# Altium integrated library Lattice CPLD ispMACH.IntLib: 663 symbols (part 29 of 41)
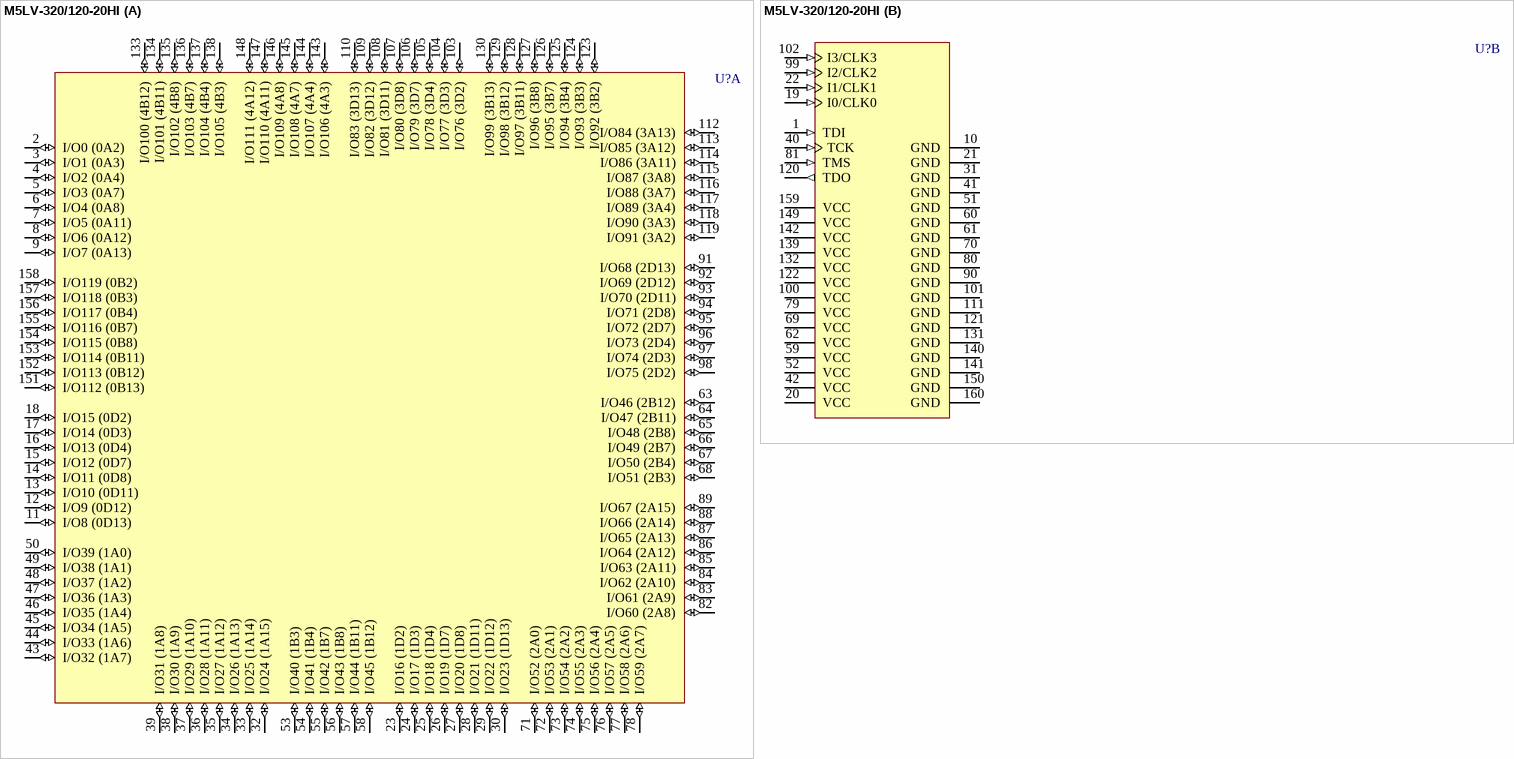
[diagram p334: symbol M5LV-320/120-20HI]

## M5LV-320/120-20HI
designator U?
High-Density and High-I/O Complex PLD
footprint MQFP160_N (QFP, 160-Leads, Body 27.7 x 27.7mm, Pitch 0.65mm, IPC Medium Density)
footprint MQFP160_L (QFP, 160-Leads, Body 27.7 x 27.7mm, Pitch 0.65mm, IPC High Density)
footprint MQFP160_M (QFP, 160-Leads, Body 27.7 x 27.7mm, Pitch 0.65mm, IPC Low Density)
3D model M5LV-MQFP160 (160-Pin Quad Flat Pack 0.65 mm Pitch)
part A pins: 2 I/O0 (0A2) (io), 3 I/O1 (0A3) (io), 4 I/O2 (0A4) (io), 5 I/O3 (0A7) (io), 6 I/O4 (0A8) (io), 7 I/O5 (0A11) (io), 8 I/O6 (0A12) (io), 9 I/O7 (0A13) (io), 11 I/O8 (0D13) (io), 12 I/O9 (0D12) (io), 13 I/O10 (0D11) (io), 14 I/O11 (0D8) (io), 15 I/O12 (0D7) (io), 16 I/O13 (0D4) (io), 17 I/O14 (0D3) (io), 18 I/O15 (0D2) (io), 23 I/O16 (1D2) (io), 24 I/O17 (1D3) (io), 25 I/O18 (1D4) (io), 26 I/O19 (1D7) (io), 27 I/O20 (1D8) (io), 28 I/O21 (1D11) (io), 29 I/O22 (1D12) (io), 30 I/O23 (1D13) (io), 32 I/O24 (1A15) (io), 33 I/O25 (1A14) (io), 34 I/O26 (1A13) (io), 35 I/O27 (1A12) (io), 36 I/O28 (1A11) (io), 37 I/O29 (1A10) (io), 38 I/O30 (1A9) (io), 39 I/O31 (1A8) (io), 43 I/O32 (1A7) (io), 44 I/O33 (1A6) (io), 45 I/O34 (1A5) (io), 46 I/O35 (1A4) (io), 47 I/O36 (1A3) (io), 48 I/O37 (1A2) (io), 49 I/O38 (1A1) (io), 50 I/O39 (1A0) (io), 53 I/O40 (1B3) (io), 54 I/O41 (1B4) (io), 55 I/O42 (1B7) (io), 56 I/O43 (1B8) (io), 57 I/O44 (1B11) (io), 58 I/O45 (1B12) (io), 63 I/O46 (2B12) (io), 64 I/O47 (2B11) (io), 65 I/O48 (2B8) (io), 66 I/O49 (2B7) (io), 67 I/O50 (2B4) (io), 68 I/O51 (2B3) (io), 71 I/O52 (2A0) (io), 72 I/O53 (2A1) (io), 73 I/O54 (2A2) (io), 74 I/O55 (2A3) (io), 75 I/O56 (2A4) (io), 76 I/O57 (2A5) (io), 77 I/O58 (2A6) (io), 78 I/O59 (2A7) (io), 82 I/O60 (2A8) (io), 83 I/O61 (2A9) (io), 84 I/O62 (2A10) (io), 85 I/O63 (2A11) (io), 86 I/O64 (2A12) (io), 87 I/O65 (2A13) (io), 88 I/O66 (2A14) (io), 89 I/O67 (2A15) (io), 91 I/O68 (2D13) (io), 92 I/O69 (2D12) (io), 93 I/O70 (2D11) (io), 94 I/O71 (2D8) (io), 95 I/O72 (2D7) (io), 96 I/O73 (2D4) (io), 97 I/O74 (2D3) (io), 98 I/O75 (2D2) (io), 103 I/O76 (3D2) (io), 104 I/O77 (3D3) (io), 105 I/O78 (3D4) (io), 106 I/O79 (3D7) (io), 107 I/O80 (3D8) (io), 108 I/O81 (3D11) (io), 109 I/O82 (3D12) (io), 110 I/O83 (3D13) (io), 112 I/O84 (3A13) (io), 113 I/O85 (3A12) (io), 114 I/O86 (3A11) (io), 115 I/O87 (3A8) (io), 116 I/O88 (3A7) (io), 117 I/O89 (3A4) (io), 118 I/O90 (3A3) (io), 119 I/O91 (3A2) (io), 123 I/O92 (3B2) (io), 124 I/O93 (3B3) (io), 125 I/O94 (3B4) (io), 126 I/O95 (3B7) (io), 127 I/O96 (3B8) (io), 128 I/O97 (3B11) (io), 129 I/O98 (3B12) (io), 130 I/O99 (3B13) (io), 133 I/O100 (4B12) (io), 134 I/O101 (4B11) (io), 135 I/O102 (4B8) (io), 136 I/O103 (4B7) (io), 137 I/O104 (4B4) (io), 138 I/O105 (4B3) (io), 143 I/O106 (4A3) (io), 144 I/O107 (4A4) (io), 145 I/O108 (4A7) (io), 146 I/O109 (4A8) (io), 147 I/O110 (4A11) (io), 148 I/O111 (4A12) (io), 151 I/O112 (0B13) (io), 152 I/O113 (0B12) (io), 153 I/O114 (0B11) (io), 154 I/O115 (0B8) (io), 155 I/O116 (0B7) (io), 156 I/O117 (0B4) (io), 157 I/O118 (0B3) (io), 158 I/O119 (0B2) (io)
part B pins: 1 TDI (in), 10 GND (power), 19 I0/CLK0 (in), 20 VCC (power), 21 GND (power), 22 I1/CLK1 (in), 31 GND (power), 40 TCK (in), 41 GND (power), 42 VCC (power), 51 GND (power), 52 VCC (power), 59 VCC (power), 60 GND (power), 61 GND (power), 62 VCC (power), 69 VCC (power), 70 GND (power), 79 VCC (power), 80 GND (power), 81 TMS (in), 90 GND (power), 99 I2/CLK2 (in), 100 VCC (power), 101 GND (power), 102 I3/CLK3 (in), 111 GND (power), 120 TDO (out), 121 GND (power), 122 VCC (power), 131 GND (power), 132 VCC (power), 139 VCC (power), 140 GND (power), 141 GND (power), 142 VCC (power), 149 VCC (power), 150 GND (power), 159 VCC (power), 160 GND (power)

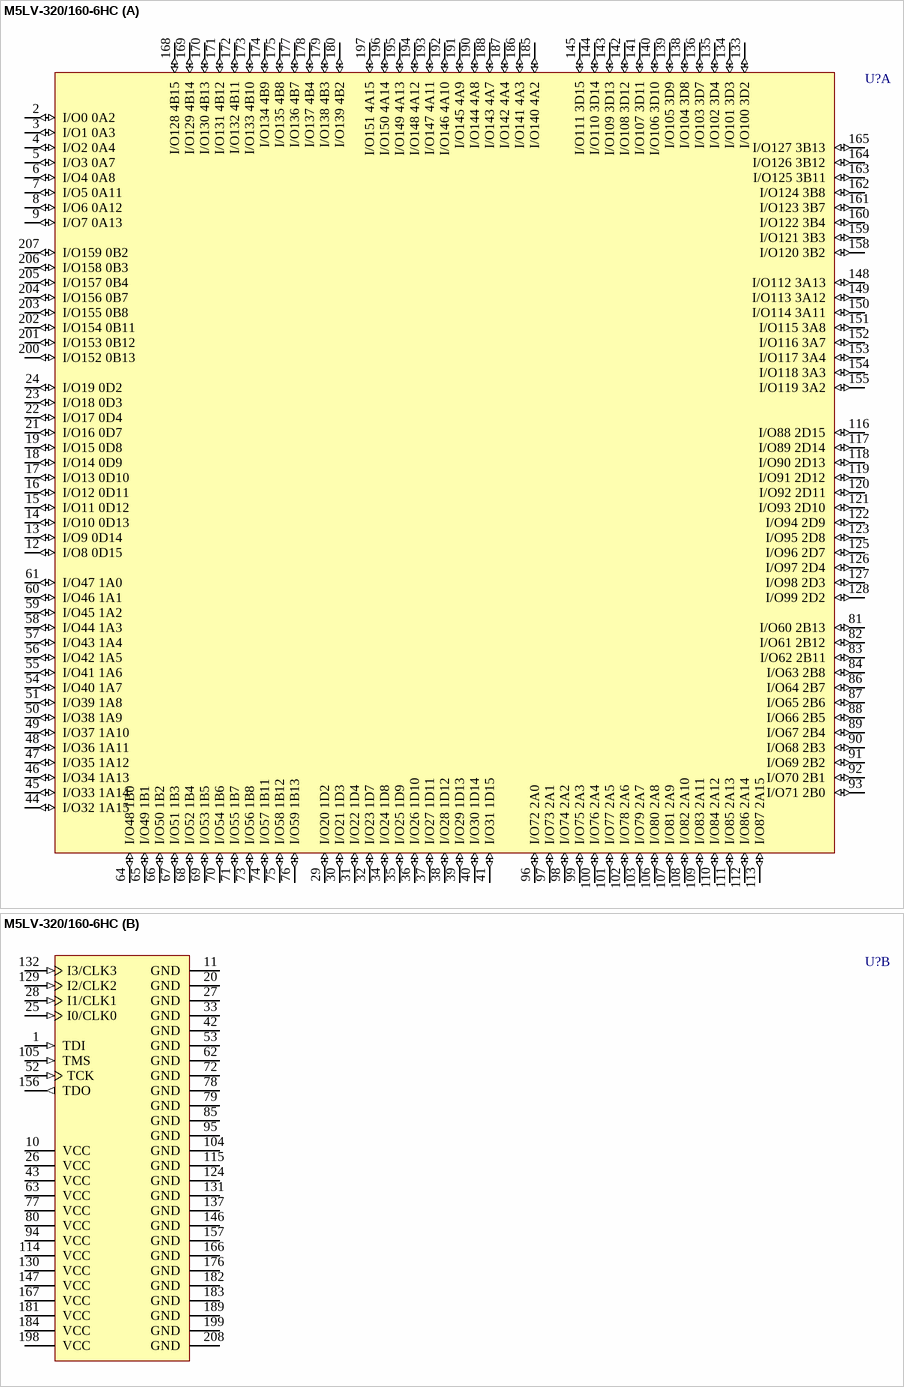
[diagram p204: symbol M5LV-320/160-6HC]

## M5LV-320/160-6HC
designator U?
High-Density and High-I/O Complex PLD
footprint MQFP208_N (Shrink QFP, 208-Leads, Body 27.7x27.7mm, Pitch 0.5mm, IPC Medium Density)
footprint MQFP208_L (Shrink QFP, 208-Leads, Body 27.7x27.7mm, Pitch 0.5mm, IPC High Density)
footprint MQFP208_M (Shrink QFP, 208-Leads, Body 27.7x27.7mm, Pitch 0.5mm, IPC Low Density)
3D model M5LV-MQFP208 (208-Pin Shrink Quad Flat Pack 0.5 mm Pitch)
part A pins: 2 I/O0 0A2 (io), 3 I/O1 0A3 (io), 4 I/O2 0A4 (io), 5 I/O3 0A7 (io), 6 I/O4 0A8 (io), 7 I/O5 0A11 (io), 8 I/O6 0A12 (io), 9 I/O7 0A13 (io), 12 I/O8 0D15 (io), 13 I/O9 0D14 (io), 14 I/O10 0D13 (io), 15 I/O11 0D12 (io), 16 I/O12 0D11 (io), 17 I/O13 0D10 (io), 18 I/O14 0D9 (io), 19 I/O15 0D8 (io), 21 I/O16 0D7 (io), 22 I/O17 0D4 (io), 23 I/O18 0D3 (io), 24 I/O19 0D2 (io), 29 I/O20 1D2 (io), 30 I/O21 1D3 (io), 31 I/O22 1D4 (io), 32 I/O23 1D7 (io), 34 I/O24 1D8 (io), 35 I/O25 1D9 (io), 36 I/O26 1D10 (io), 37 I/O27 1D11 (io), 38 I/O28 1D12 (io), 39 I/O29 1D13 (io), 40 I/O30 1D14 (io), 41 I/O31 1D15 (io), 44 I/O32 1A15 (io), 45 I/O33 1A14 (io), 46 I/O34 1A13 (io), 47 I/O35 1A12 (io), 48 I/O36 1A11 (io), 49 I/O37 1A10 (io), 50 I/O38 1A9 (io), 51 I/O39 1A8 (io), 54 I/O40 1A7 (io), 55 I/O41 1A6 (io), 56 I/O42 1A5 (io), 57 I/O43 1A4 (io), 58 I/O44 1A3 (io), 59 I/O45 1A2 (io), 60 I/O46 1A1 (io), 61 I/O47 1A0 (io), 64 I/O48 1B0 (io), 65 I/O49 1B1 (io), 66 I/O50 1B2 (io), 67 I/O51 1B3 (io), 68 I/O52 1B4 (io), 69 I/O53 1B5 (io), 70 I/O54 1B6 (io), 71 I/O55 1B7 (io), 73 I/O56 1B8 (io), 74 I/O57 1B11 (io), 75 I/O58 1B12 (io), 76 I/O59 1B13 (io), 81 I/O60 2B13 (io), 82 I/O61 2B12 (io), 83 I/O62 2B11 (io), 84 I/O63 2B8 (io), 86 I/O64 2B7 (io), 87 I/O65 2B6 (io), 88 I/O66 2B5 (io), 89 I/O67 2B4 (io), 90 I/O68 2B3 (io), 91 I/O69 2B2 (io), 92 I/O70 2B1 (io), 93 I/O71 2B0 (io), 96 I/O72 2A0 (io), 97 I/O73 2A1 (io), 98 I/O74 2A2 (io), 99 I/O75 2A3 (io), 100 I/O76 2A4 (io), 101 I/O77 2A5 (io), 102 I/O78 2A6 (io), 103 I/O79 2A7 (io), 106 I/O80 2A8 (io), 107 I/O81 2A9 (io), 108 I/O82 2A10 (io), 109 I/O83 2A11 (io), 110 I/O84 2A12 (io), 111 I/O85 2A13 (io), 112 I/O86 2A14 (io), 113 I/O87 2A15 (io), 116 I/O88 2D15 (io), 117 I/O89 2D14 (io), 118 I/O90 2D13 (io), 119 I/O91 2D12 (io), 120 I/O92 2D11 (io), 121 I/O93 2D10 (io), 122 I/O94 2D9 (io), 123 I/O95 2D8 (io), 125 I/O96 2D7 (io), 126 I/O97 2D4 (io), 127 I/O98 2D3 (io), 128 I/O99 2D2 (io), 133 I/O100 3D2 (io), 134 I/O101 3D3 (io), 135 I/O102 3D4 (io), 136 I/O103 3D7 (io), 138 I/O104 3D8 (io), 139 I/O105 3D9 (io), 140 I/O106 3D10 (io), 141 I/O107 3D11 (io), 142 I/O108 3D12 (io), 143 I/O109 3D13 (io), 144 I/O110 3D14 (io), 145 I/O111 3D15 (io), 148 I/O112 3A13 (io), 149 I/O113 3A12 (io), 150 I/O114 3A11 (io), 151 I/O115 3A8 (io), 152 I/O116 3A7 (io), 153 I/O117 3A4 (io), 154 I/O118 3A3 (io), 155 I/O119 3A2 (io), 158 I/O120 3B2 (io), 159 I/O121 3B3 (io), 160 I/O122 3B4 (io), 161 I/O123 3B7 (io), 162 I/O124 3B8 (io), 163 I/O125 3B11 (io), 164 I/O126 3B12 (io), 165 I/O127 3B13 (io), 168 I/O128 4B15 (io), 169 I/O129 4B14 (io), 170 I/O130 4B13 (io), 171 I/O131 4B12 (io), 172 I/O132 4B11 (io), 173 I/O133 4B10 (io), 174 I/O134 4B9 (io), 175 I/O135 4B8 (io), 177 I/O136 4B7 (io), 178 I/O137 4B4 (io), 179 I/O138 4B3 (io), 180 I/O139 4B2 (io), 185 I/O140 4A2 (io), 186 I/O141 4A3 (io), 187 I/O142 4A4 (io), 188 I/O143 4A7 (io), 190 I/O144 4A8 (io), 191 I/O145 4A9 (io), 192 I/O146 4A10 (io), 193 I/O147 4A11 (io), 194 I/O148 4A12 (io), 195 I/O149 4A13 (io), 196 I/O150 4A14 (io), 197 I/O151 4A15 (io), 200 I/O152 0B13 (io), 201 I/O153 0B12 (io), 202 I/O154 0B11 (io), 203 I/O155 0B8 (io), 204 I/O156 0B7 (io), 205 I/O157 0B4 (io), 206 I/O158 0B3 (io), 207 I/O159 0B2 (io)
part B pins: 1 TDI (in), 10 VCC (power), 11 GND (power), 20 GND (power), 25 I0/CLK0 (in), 26 VCC (power), 27 GND (power), 28 I1/CLK1 (in), 33 GND (power), 42 GND (power), 43 VCC (power), 52 TCK (in), 53 GND (power), 62 GND (power), 63 VCC (power), 72 GND (power), 77 VCC (power), 78 GND (power), 79 GND (power), 80 VCC (power), 85 GND (power), 94 VCC (power), 95 GND (power), 104 GND (power), 105 TMS (in), 114 VCC (power), 115 GND (power), 124 GND (power), 129 I2/CLK2 (in), 130 VCC (power), 131 GND (power), 132 I3/CLK3 (in), 137 GND (power), 146 GND (power), 147 VCC (power), 156 TDO (out), 157 GND (power), 166 GND (power), 167 VCC (power), 176 GND (power), 181 VCC (power), 182 GND (power), 183 GND (power), 184 VCC (power), 189 GND (power), 198 VCC (power), 199 GND (power), 208 GND (power)

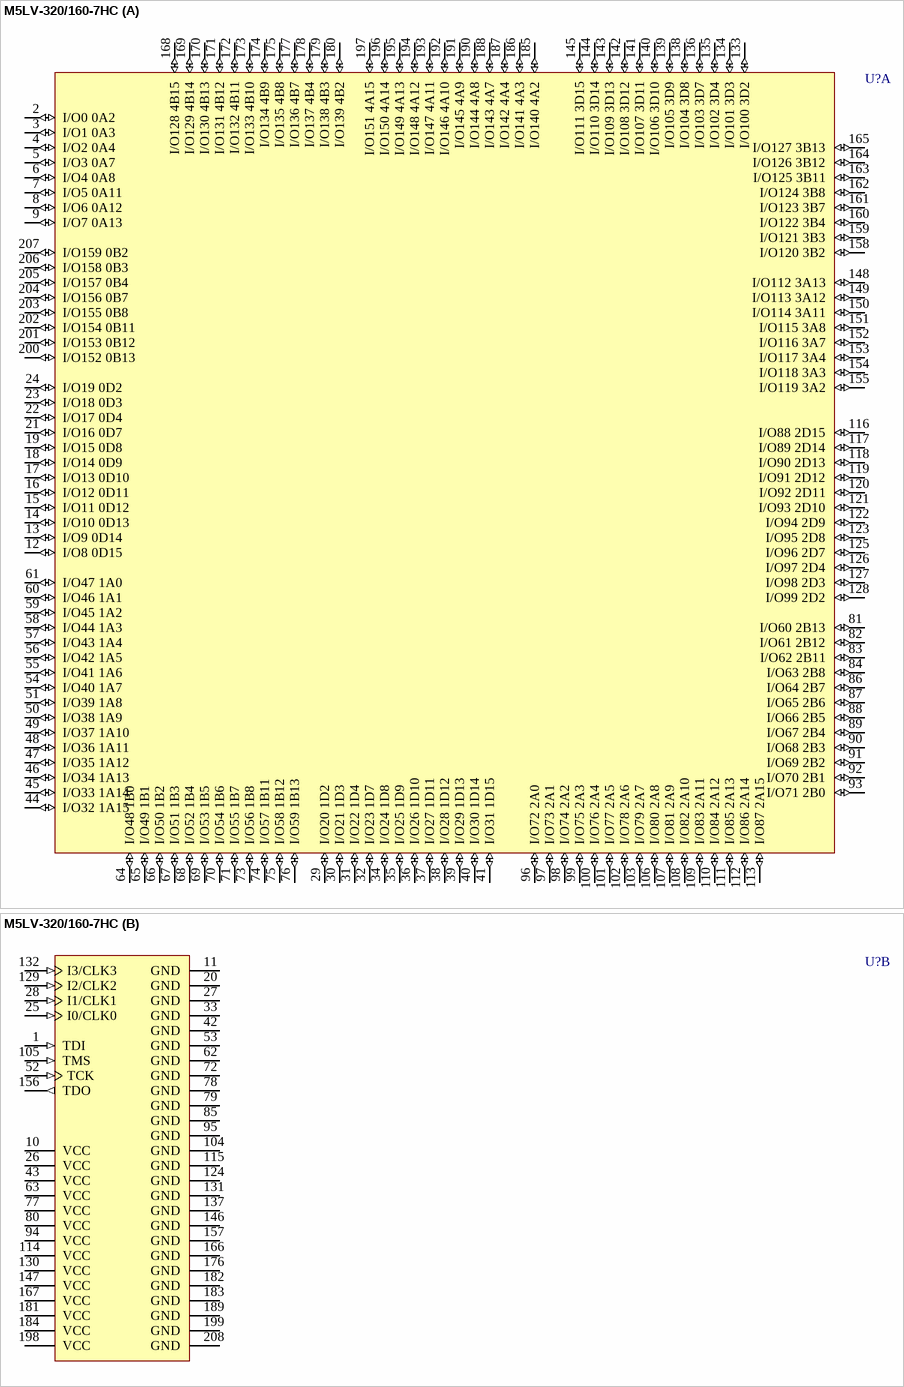
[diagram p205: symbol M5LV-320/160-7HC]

## M5LV-320/160-7HC
designator U?
High-Density and High-I/O Complex PLD
footprint MQFP208_N (Shrink QFP, 208-Leads, Body 27.7x27.7mm, Pitch 0.5mm, IPC Medium Density)
footprint MQFP208_L (Shrink QFP, 208-Leads, Body 27.7x27.7mm, Pitch 0.5mm, IPC High Density)
footprint MQFP208_M (Shrink QFP, 208-Leads, Body 27.7x27.7mm, Pitch 0.5mm, IPC Low Density)
3D model M5LV-MQFP208 (208-Pin Shrink Quad Flat Pack 0.5 mm Pitch)
part A pins: 2 I/O0 0A2 (io), 3 I/O1 0A3 (io), 4 I/O2 0A4 (io), 5 I/O3 0A7 (io), 6 I/O4 0A8 (io), 7 I/O5 0A11 (io), 8 I/O6 0A12 (io), 9 I/O7 0A13 (io), 12 I/O8 0D15 (io), 13 I/O9 0D14 (io), 14 I/O10 0D13 (io), 15 I/O11 0D12 (io), 16 I/O12 0D11 (io), 17 I/O13 0D10 (io), 18 I/O14 0D9 (io), 19 I/O15 0D8 (io), 21 I/O16 0D7 (io), 22 I/O17 0D4 (io), 23 I/O18 0D3 (io), 24 I/O19 0D2 (io), 29 I/O20 1D2 (io), 30 I/O21 1D3 (io), 31 I/O22 1D4 (io), 32 I/O23 1D7 (io), 34 I/O24 1D8 (io), 35 I/O25 1D9 (io), 36 I/O26 1D10 (io), 37 I/O27 1D11 (io), 38 I/O28 1D12 (io), 39 I/O29 1D13 (io), 40 I/O30 1D14 (io), 41 I/O31 1D15 (io), 44 I/O32 1A15 (io), 45 I/O33 1A14 (io), 46 I/O34 1A13 (io), 47 I/O35 1A12 (io), 48 I/O36 1A11 (io), 49 I/O37 1A10 (io), 50 I/O38 1A9 (io), 51 I/O39 1A8 (io), 54 I/O40 1A7 (io), 55 I/O41 1A6 (io), 56 I/O42 1A5 (io), 57 I/O43 1A4 (io), 58 I/O44 1A3 (io), 59 I/O45 1A2 (io), 60 I/O46 1A1 (io), 61 I/O47 1A0 (io), 64 I/O48 1B0 (io), 65 I/O49 1B1 (io), 66 I/O50 1B2 (io), 67 I/O51 1B3 (io), 68 I/O52 1B4 (io), 69 I/O53 1B5 (io), 70 I/O54 1B6 (io), 71 I/O55 1B7 (io), 73 I/O56 1B8 (io), 74 I/O57 1B11 (io), 75 I/O58 1B12 (io), 76 I/O59 1B13 (io), 81 I/O60 2B13 (io), 82 I/O61 2B12 (io), 83 I/O62 2B11 (io), 84 I/O63 2B8 (io), 86 I/O64 2B7 (io), 87 I/O65 2B6 (io), 88 I/O66 2B5 (io), 89 I/O67 2B4 (io), 90 I/O68 2B3 (io), 91 I/O69 2B2 (io), 92 I/O70 2B1 (io), 93 I/O71 2B0 (io), 96 I/O72 2A0 (io), 97 I/O73 2A1 (io), 98 I/O74 2A2 (io), 99 I/O75 2A3 (io), 100 I/O76 2A4 (io), 101 I/O77 2A5 (io), 102 I/O78 2A6 (io), 103 I/O79 2A7 (io), 106 I/O80 2A8 (io), 107 I/O81 2A9 (io), 108 I/O82 2A10 (io), 109 I/O83 2A11 (io), 110 I/O84 2A12 (io), 111 I/O85 2A13 (io), 112 I/O86 2A14 (io), 113 I/O87 2A15 (io), 116 I/O88 2D15 (io), 117 I/O89 2D14 (io), 118 I/O90 2D13 (io), 119 I/O91 2D12 (io), 120 I/O92 2D11 (io), 121 I/O93 2D10 (io), 122 I/O94 2D9 (io), 123 I/O95 2D8 (io), 125 I/O96 2D7 (io), 126 I/O97 2D4 (io), 127 I/O98 2D3 (io), 128 I/O99 2D2 (io), 133 I/O100 3D2 (io), 134 I/O101 3D3 (io), 135 I/O102 3D4 (io), 136 I/O103 3D7 (io), 138 I/O104 3D8 (io), 139 I/O105 3D9 (io), 140 I/O106 3D10 (io), 141 I/O107 3D11 (io), 142 I/O108 3D12 (io), 143 I/O109 3D13 (io), 144 I/O110 3D14 (io), 145 I/O111 3D15 (io), 148 I/O112 3A13 (io), 149 I/O113 3A12 (io), 150 I/O114 3A11 (io), 151 I/O115 3A8 (io), 152 I/O116 3A7 (io), 153 I/O117 3A4 (io), 154 I/O118 3A3 (io), 155 I/O119 3A2 (io), 158 I/O120 3B2 (io), 159 I/O121 3B3 (io), 160 I/O122 3B4 (io), 161 I/O123 3B7 (io), 162 I/O124 3B8 (io), 163 I/O125 3B11 (io), 164 I/O126 3B12 (io), 165 I/O127 3B13 (io), 168 I/O128 4B15 (io), 169 I/O129 4B14 (io), 170 I/O130 4B13 (io), 171 I/O131 4B12 (io), 172 I/O132 4B11 (io), 173 I/O133 4B10 (io), 174 I/O134 4B9 (io), 175 I/O135 4B8 (io), 177 I/O136 4B7 (io), 178 I/O137 4B4 (io), 179 I/O138 4B3 (io), 180 I/O139 4B2 (io), 185 I/O140 4A2 (io), 186 I/O141 4A3 (io), 187 I/O142 4A4 (io), 188 I/O143 4A7 (io), 190 I/O144 4A8 (io), 191 I/O145 4A9 (io), 192 I/O146 4A10 (io), 193 I/O147 4A11 (io), 194 I/O148 4A12 (io), 195 I/O149 4A13 (io), 196 I/O150 4A14 (io), 197 I/O151 4A15 (io), 200 I/O152 0B13 (io), 201 I/O153 0B12 (io), 202 I/O154 0B11 (io), 203 I/O155 0B8 (io), 204 I/O156 0B7 (io), 205 I/O157 0B4 (io), 206 I/O158 0B3 (io), 207 I/O159 0B2 (io)
part B pins: 1 TDI (in), 10 VCC (power), 11 GND (power), 20 GND (power), 25 I0/CLK0 (in), 26 VCC (power), 27 GND (power), 28 I1/CLK1 (in), 33 GND (power), 42 GND (power), 43 VCC (power), 52 TCK (in), 53 GND (power), 62 GND (power), 63 VCC (power), 72 GND (power), 77 VCC (power), 78 GND (power), 79 GND (power), 80 VCC (power), 85 GND (power), 94 VCC (power), 95 GND (power), 104 GND (power), 105 TMS (in), 114 VCC (power), 115 GND (power), 124 GND (power), 129 I2/CLK2 (in), 130 VCC (power), 131 GND (power), 132 I3/CLK3 (in), 137 GND (power), 146 GND (power), 147 VCC (power), 156 TDO (out), 157 GND (power), 166 GND (power), 167 VCC (power), 176 GND (power), 181 VCC (power), 182 GND (power), 183 GND (power), 184 VCC (power), 189 GND (power), 198 VCC (power), 199 GND (power), 208 GND (power)

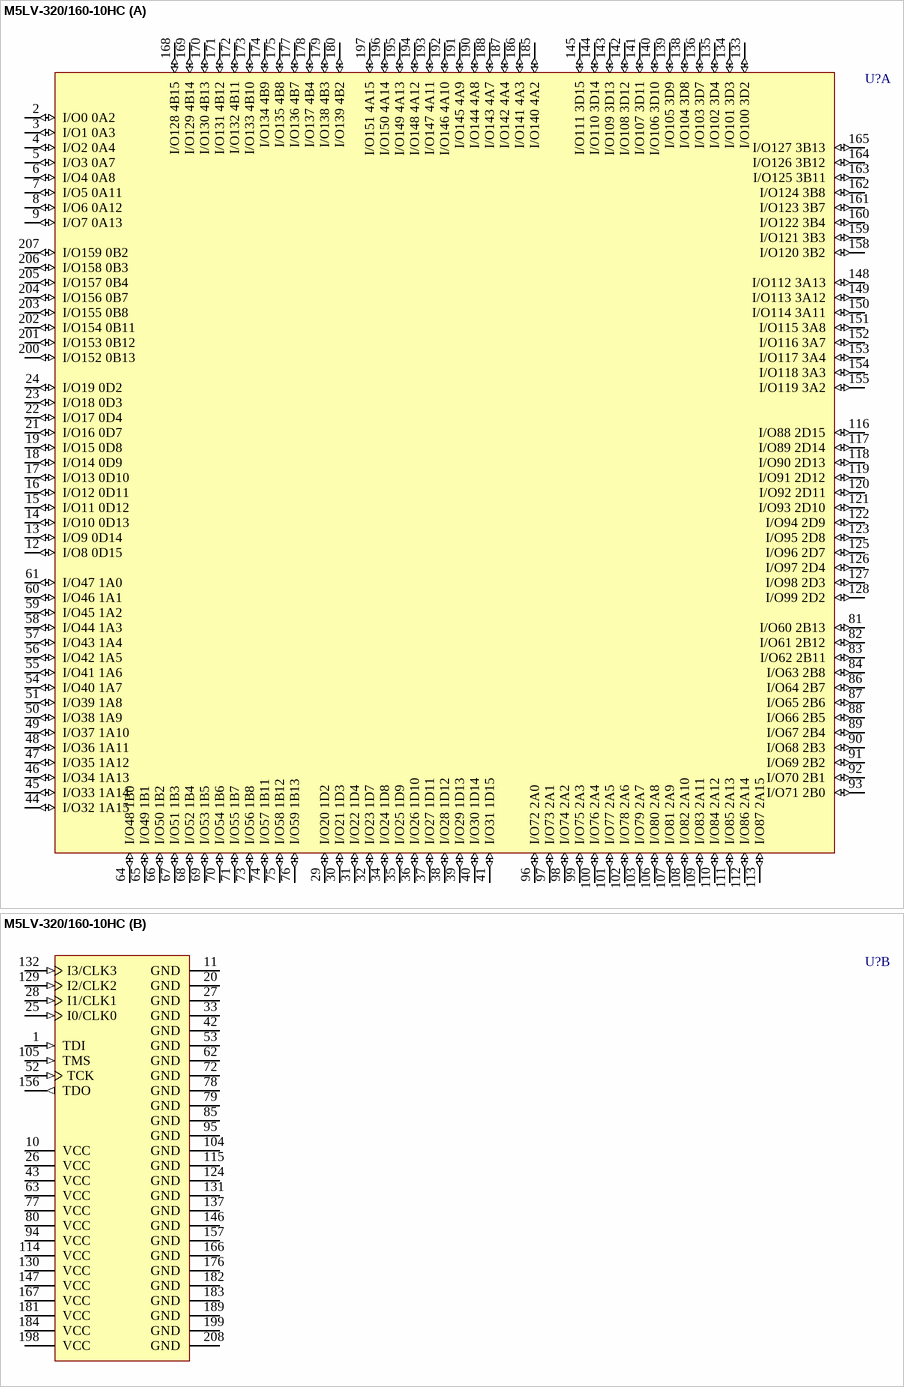
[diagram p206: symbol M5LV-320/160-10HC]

## M5LV-320/160-10HC
designator U?
High-Density and High-I/O Complex PLD
footprint MQFP208_N (Shrink QFP, 208-Leads, Body 27.7x27.7mm, Pitch 0.5mm, IPC Medium Density)
footprint MQFP208_L (Shrink QFP, 208-Leads, Body 27.7x27.7mm, Pitch 0.5mm, IPC High Density)
footprint MQFP208_M (Shrink QFP, 208-Leads, Body 27.7x27.7mm, Pitch 0.5mm, IPC Low Density)
3D model M5LV-MQFP208 (208-Pin Shrink Quad Flat Pack 0.5 mm Pitch)
part A pins: 2 I/O0 0A2 (io), 3 I/O1 0A3 (io), 4 I/O2 0A4 (io), 5 I/O3 0A7 (io), 6 I/O4 0A8 (io), 7 I/O5 0A11 (io), 8 I/O6 0A12 (io), 9 I/O7 0A13 (io), 12 I/O8 0D15 (io), 13 I/O9 0D14 (io), 14 I/O10 0D13 (io), 15 I/O11 0D12 (io), 16 I/O12 0D11 (io), 17 I/O13 0D10 (io), 18 I/O14 0D9 (io), 19 I/O15 0D8 (io), 21 I/O16 0D7 (io), 22 I/O17 0D4 (io), 23 I/O18 0D3 (io), 24 I/O19 0D2 (io), 29 I/O20 1D2 (io), 30 I/O21 1D3 (io), 31 I/O22 1D4 (io), 32 I/O23 1D7 (io), 34 I/O24 1D8 (io), 35 I/O25 1D9 (io), 36 I/O26 1D10 (io), 37 I/O27 1D11 (io), 38 I/O28 1D12 (io), 39 I/O29 1D13 (io), 40 I/O30 1D14 (io), 41 I/O31 1D15 (io), 44 I/O32 1A15 (io), 45 I/O33 1A14 (io), 46 I/O34 1A13 (io), 47 I/O35 1A12 (io), 48 I/O36 1A11 (io), 49 I/O37 1A10 (io), 50 I/O38 1A9 (io), 51 I/O39 1A8 (io), 54 I/O40 1A7 (io), 55 I/O41 1A6 (io), 56 I/O42 1A5 (io), 57 I/O43 1A4 (io), 58 I/O44 1A3 (io), 59 I/O45 1A2 (io), 60 I/O46 1A1 (io), 61 I/O47 1A0 (io), 64 I/O48 1B0 (io), 65 I/O49 1B1 (io), 66 I/O50 1B2 (io), 67 I/O51 1B3 (io), 68 I/O52 1B4 (io), 69 I/O53 1B5 (io), 70 I/O54 1B6 (io), 71 I/O55 1B7 (io), 73 I/O56 1B8 (io), 74 I/O57 1B11 (io), 75 I/O58 1B12 (io), 76 I/O59 1B13 (io), 81 I/O60 2B13 (io), 82 I/O61 2B12 (io), 83 I/O62 2B11 (io), 84 I/O63 2B8 (io), 86 I/O64 2B7 (io), 87 I/O65 2B6 (io), 88 I/O66 2B5 (io), 89 I/O67 2B4 (io), 90 I/O68 2B3 (io), 91 I/O69 2B2 (io), 92 I/O70 2B1 (io), 93 I/O71 2B0 (io), 96 I/O72 2A0 (io), 97 I/O73 2A1 (io), 98 I/O74 2A2 (io), 99 I/O75 2A3 (io), 100 I/O76 2A4 (io), 101 I/O77 2A5 (io), 102 I/O78 2A6 (io), 103 I/O79 2A7 (io), 106 I/O80 2A8 (io), 107 I/O81 2A9 (io), 108 I/O82 2A10 (io), 109 I/O83 2A11 (io), 110 I/O84 2A12 (io), 111 I/O85 2A13 (io), 112 I/O86 2A14 (io), 113 I/O87 2A15 (io), 116 I/O88 2D15 (io), 117 I/O89 2D14 (io), 118 I/O90 2D13 (io), 119 I/O91 2D12 (io), 120 I/O92 2D11 (io), 121 I/O93 2D10 (io), 122 I/O94 2D9 (io), 123 I/O95 2D8 (io), 125 I/O96 2D7 (io), 126 I/O97 2D4 (io), 127 I/O98 2D3 (io), 128 I/O99 2D2 (io), 133 I/O100 3D2 (io), 134 I/O101 3D3 (io), 135 I/O102 3D4 (io), 136 I/O103 3D7 (io), 138 I/O104 3D8 (io), 139 I/O105 3D9 (io), 140 I/O106 3D10 (io), 141 I/O107 3D11 (io), 142 I/O108 3D12 (io), 143 I/O109 3D13 (io), 144 I/O110 3D14 (io), 145 I/O111 3D15 (io), 148 I/O112 3A13 (io), 149 I/O113 3A12 (io), 150 I/O114 3A11 (io), 151 I/O115 3A8 (io), 152 I/O116 3A7 (io), 153 I/O117 3A4 (io), 154 I/O118 3A3 (io), 155 I/O119 3A2 (io), 158 I/O120 3B2 (io), 159 I/O121 3B3 (io), 160 I/O122 3B4 (io), 161 I/O123 3B7 (io), 162 I/O124 3B8 (io), 163 I/O125 3B11 (io), 164 I/O126 3B12 (io), 165 I/O127 3B13 (io), 168 I/O128 4B15 (io), 169 I/O129 4B14 (io), 170 I/O130 4B13 (io), 171 I/O131 4B12 (io), 172 I/O132 4B11 (io), 173 I/O133 4B10 (io), 174 I/O134 4B9 (io), 175 I/O135 4B8 (io), 177 I/O136 4B7 (io), 178 I/O137 4B4 (io), 179 I/O138 4B3 (io), 180 I/O139 4B2 (io), 185 I/O140 4A2 (io), 186 I/O141 4A3 (io), 187 I/O142 4A4 (io), 188 I/O143 4A7 (io), 190 I/O144 4A8 (io), 191 I/O145 4A9 (io), 192 I/O146 4A10 (io), 193 I/O147 4A11 (io), 194 I/O148 4A12 (io), 195 I/O149 4A13 (io), 196 I/O150 4A14 (io), 197 I/O151 4A15 (io), 200 I/O152 0B13 (io), 201 I/O153 0B12 (io), 202 I/O154 0B11 (io), 203 I/O155 0B8 (io), 204 I/O156 0B7 (io), 205 I/O157 0B4 (io), 206 I/O158 0B3 (io), 207 I/O159 0B2 (io)
part B pins: 1 TDI (in), 10 VCC (power), 11 GND (power), 20 GND (power), 25 I0/CLK0 (in), 26 VCC (power), 27 GND (power), 28 I1/CLK1 (in), 33 GND (power), 42 GND (power), 43 VCC (power), 52 TCK (in), 53 GND (power), 62 GND (power), 63 VCC (power), 72 GND (power), 77 VCC (power), 78 GND (power), 79 GND (power), 80 VCC (power), 85 GND (power), 94 VCC (power), 95 GND (power), 104 GND (power), 105 TMS (in), 114 VCC (power), 115 GND (power), 124 GND (power), 129 I2/CLK2 (in), 130 VCC (power), 131 GND (power), 132 I3/CLK3 (in), 137 GND (power), 146 GND (power), 147 VCC (power), 156 TDO (out), 157 GND (power), 166 GND (power), 167 VCC (power), 176 GND (power), 181 VCC (power), 182 GND (power), 183 GND (power), 184 VCC (power), 189 GND (power), 198 VCC (power), 199 GND (power), 208 GND (power)

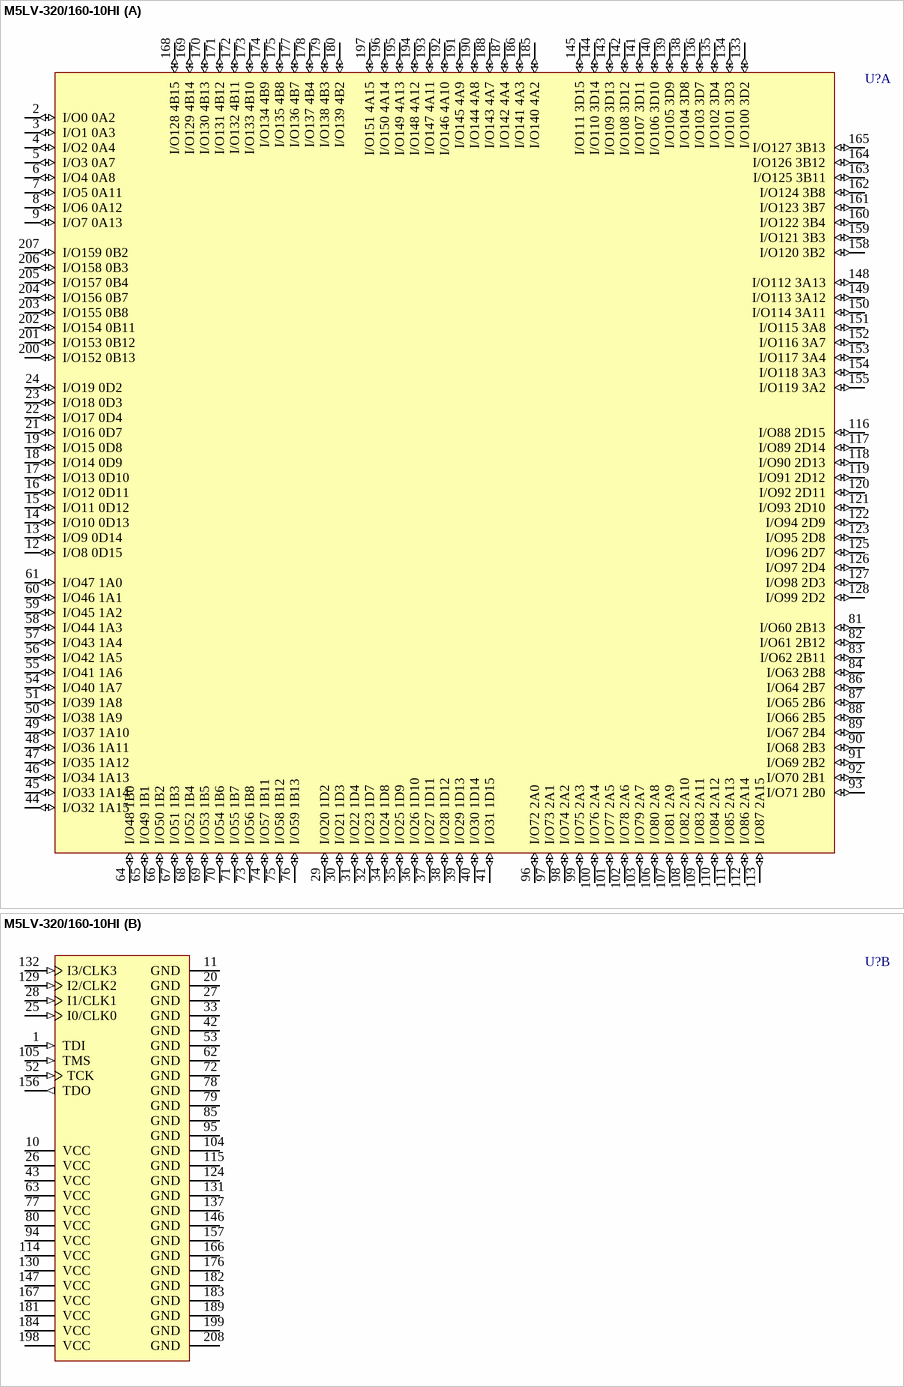
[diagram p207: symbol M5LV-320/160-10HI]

## M5LV-320/160-10HI
designator U?
High-Density and High-I/O Complex PLD
footprint MQFP208_N (Shrink QFP, 208-Leads, Body 27.7x27.7mm, Pitch 0.5mm, IPC Medium Density)
footprint MQFP208_L (Shrink QFP, 208-Leads, Body 27.7x27.7mm, Pitch 0.5mm, IPC High Density)
footprint MQFP208_M (Shrink QFP, 208-Leads, Body 27.7x27.7mm, Pitch 0.5mm, IPC Low Density)
3D model M5LV-MQFP208 (208-Pin Shrink Quad Flat Pack 0.5 mm Pitch)
part A pins: 2 I/O0 0A2 (io), 3 I/O1 0A3 (io), 4 I/O2 0A4 (io), 5 I/O3 0A7 (io), 6 I/O4 0A8 (io), 7 I/O5 0A11 (io), 8 I/O6 0A12 (io), 9 I/O7 0A13 (io), 12 I/O8 0D15 (io), 13 I/O9 0D14 (io), 14 I/O10 0D13 (io), 15 I/O11 0D12 (io), 16 I/O12 0D11 (io), 17 I/O13 0D10 (io), 18 I/O14 0D9 (io), 19 I/O15 0D8 (io), 21 I/O16 0D7 (io), 22 I/O17 0D4 (io), 23 I/O18 0D3 (io), 24 I/O19 0D2 (io), 29 I/O20 1D2 (io), 30 I/O21 1D3 (io), 31 I/O22 1D4 (io), 32 I/O23 1D7 (io), 34 I/O24 1D8 (io), 35 I/O25 1D9 (io), 36 I/O26 1D10 (io), 37 I/O27 1D11 (io), 38 I/O28 1D12 (io), 39 I/O29 1D13 (io), 40 I/O30 1D14 (io), 41 I/O31 1D15 (io), 44 I/O32 1A15 (io), 45 I/O33 1A14 (io), 46 I/O34 1A13 (io), 47 I/O35 1A12 (io), 48 I/O36 1A11 (io), 49 I/O37 1A10 (io), 50 I/O38 1A9 (io), 51 I/O39 1A8 (io), 54 I/O40 1A7 (io), 55 I/O41 1A6 (io), 56 I/O42 1A5 (io), 57 I/O43 1A4 (io), 58 I/O44 1A3 (io), 59 I/O45 1A2 (io), 60 I/O46 1A1 (io), 61 I/O47 1A0 (io), 64 I/O48 1B0 (io), 65 I/O49 1B1 (io), 66 I/O50 1B2 (io), 67 I/O51 1B3 (io), 68 I/O52 1B4 (io), 69 I/O53 1B5 (io), 70 I/O54 1B6 (io), 71 I/O55 1B7 (io), 73 I/O56 1B8 (io), 74 I/O57 1B11 (io), 75 I/O58 1B12 (io), 76 I/O59 1B13 (io), 81 I/O60 2B13 (io), 82 I/O61 2B12 (io), 83 I/O62 2B11 (io), 84 I/O63 2B8 (io), 86 I/O64 2B7 (io), 87 I/O65 2B6 (io), 88 I/O66 2B5 (io), 89 I/O67 2B4 (io), 90 I/O68 2B3 (io), 91 I/O69 2B2 (io), 92 I/O70 2B1 (io), 93 I/O71 2B0 (io), 96 I/O72 2A0 (io), 97 I/O73 2A1 (io), 98 I/O74 2A2 (io), 99 I/O75 2A3 (io), 100 I/O76 2A4 (io), 101 I/O77 2A5 (io), 102 I/O78 2A6 (io), 103 I/O79 2A7 (io), 106 I/O80 2A8 (io), 107 I/O81 2A9 (io), 108 I/O82 2A10 (io), 109 I/O83 2A11 (io), 110 I/O84 2A12 (io), 111 I/O85 2A13 (io), 112 I/O86 2A14 (io), 113 I/O87 2A15 (io), 116 I/O88 2D15 (io), 117 I/O89 2D14 (io), 118 I/O90 2D13 (io), 119 I/O91 2D12 (io), 120 I/O92 2D11 (io), 121 I/O93 2D10 (io), 122 I/O94 2D9 (io), 123 I/O95 2D8 (io), 125 I/O96 2D7 (io), 126 I/O97 2D4 (io), 127 I/O98 2D3 (io), 128 I/O99 2D2 (io), 133 I/O100 3D2 (io), 134 I/O101 3D3 (io), 135 I/O102 3D4 (io), 136 I/O103 3D7 (io), 138 I/O104 3D8 (io), 139 I/O105 3D9 (io), 140 I/O106 3D10 (io), 141 I/O107 3D11 (io), 142 I/O108 3D12 (io), 143 I/O109 3D13 (io), 144 I/O110 3D14 (io), 145 I/O111 3D15 (io), 148 I/O112 3A13 (io), 149 I/O113 3A12 (io), 150 I/O114 3A11 (io), 151 I/O115 3A8 (io), 152 I/O116 3A7 (io), 153 I/O117 3A4 (io), 154 I/O118 3A3 (io), 155 I/O119 3A2 (io), 158 I/O120 3B2 (io), 159 I/O121 3B3 (io), 160 I/O122 3B4 (io), 161 I/O123 3B7 (io), 162 I/O124 3B8 (io), 163 I/O125 3B11 (io), 164 I/O126 3B12 (io), 165 I/O127 3B13 (io), 168 I/O128 4B15 (io), 169 I/O129 4B14 (io), 170 I/O130 4B13 (io), 171 I/O131 4B12 (io), 172 I/O132 4B11 (io), 173 I/O133 4B10 (io), 174 I/O134 4B9 (io), 175 I/O135 4B8 (io), 177 I/O136 4B7 (io), 178 I/O137 4B4 (io), 179 I/O138 4B3 (io), 180 I/O139 4B2 (io), 185 I/O140 4A2 (io), 186 I/O141 4A3 (io), 187 I/O142 4A4 (io), 188 I/O143 4A7 (io), 190 I/O144 4A8 (io), 191 I/O145 4A9 (io), 192 I/O146 4A10 (io), 193 I/O147 4A11 (io), 194 I/O148 4A12 (io), 195 I/O149 4A13 (io), 196 I/O150 4A14 (io), 197 I/O151 4A15 (io), 200 I/O152 0B13 (io), 201 I/O153 0B12 (io), 202 I/O154 0B11 (io), 203 I/O155 0B8 (io), 204 I/O156 0B7 (io), 205 I/O157 0B4 (io), 206 I/O158 0B3 (io), 207 I/O159 0B2 (io)
part B pins: 1 TDI (in), 10 VCC (power), 11 GND (power), 20 GND (power), 25 I0/CLK0 (in), 26 VCC (power), 27 GND (power), 28 I1/CLK1 (in), 33 GND (power), 42 GND (power), 43 VCC (power), 52 TCK (in), 53 GND (power), 62 GND (power), 63 VCC (power), 72 GND (power), 77 VCC (power), 78 GND (power), 79 GND (power), 80 VCC (power), 85 GND (power), 94 VCC (power), 95 GND (power), 104 GND (power), 105 TMS (in), 114 VCC (power), 115 GND (power), 124 GND (power), 129 I2/CLK2 (in), 130 VCC (power), 131 GND (power), 132 I3/CLK3 (in), 137 GND (power), 146 GND (power), 147 VCC (power), 156 TDO (out), 157 GND (power), 166 GND (power), 167 VCC (power), 176 GND (power), 181 VCC (power), 182 GND (power), 183 GND (power), 184 VCC (power), 189 GND (power), 198 VCC (power), 199 GND (power), 208 GND (power)

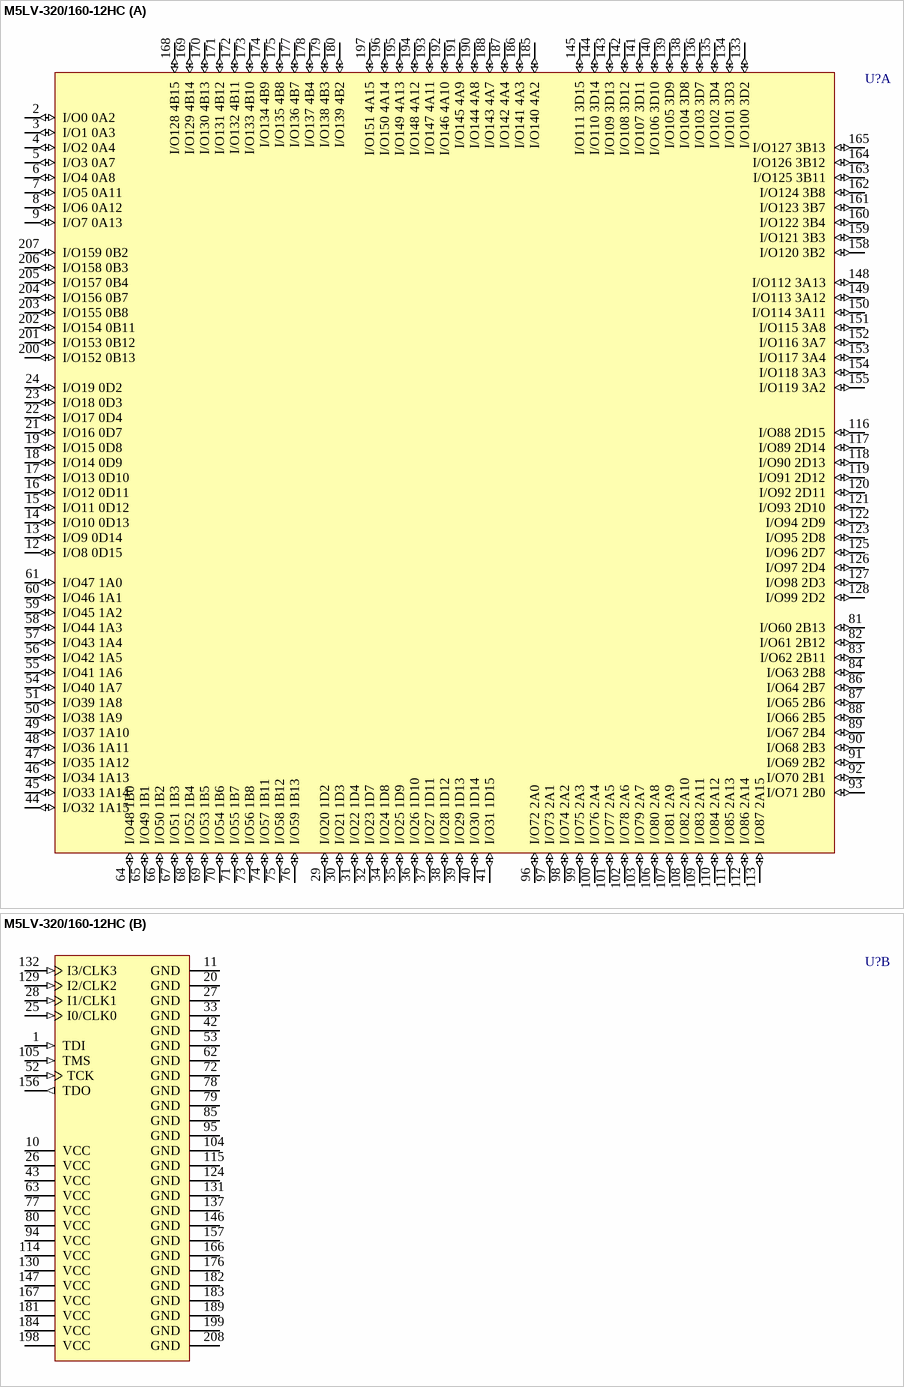
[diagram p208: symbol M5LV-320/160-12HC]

## M5LV-320/160-12HC
designator U?
High-Density and High-I/O Complex PLD
footprint MQFP208_N (Shrink QFP, 208-Leads, Body 27.7x27.7mm, Pitch 0.5mm, IPC Medium Density)
footprint MQFP208_L (Shrink QFP, 208-Leads, Body 27.7x27.7mm, Pitch 0.5mm, IPC High Density)
footprint MQFP208_M (Shrink QFP, 208-Leads, Body 27.7x27.7mm, Pitch 0.5mm, IPC Low Density)
3D model M5LV-MQFP208 (208-Pin Shrink Quad Flat Pack 0.5 mm Pitch)
part A pins: 2 I/O0 0A2 (io), 3 I/O1 0A3 (io), 4 I/O2 0A4 (io), 5 I/O3 0A7 (io), 6 I/O4 0A8 (io), 7 I/O5 0A11 (io), 8 I/O6 0A12 (io), 9 I/O7 0A13 (io), 12 I/O8 0D15 (io), 13 I/O9 0D14 (io), 14 I/O10 0D13 (io), 15 I/O11 0D12 (io), 16 I/O12 0D11 (io), 17 I/O13 0D10 (io), 18 I/O14 0D9 (io), 19 I/O15 0D8 (io), 21 I/O16 0D7 (io), 22 I/O17 0D4 (io), 23 I/O18 0D3 (io), 24 I/O19 0D2 (io), 29 I/O20 1D2 (io), 30 I/O21 1D3 (io), 31 I/O22 1D4 (io), 32 I/O23 1D7 (io), 34 I/O24 1D8 (io), 35 I/O25 1D9 (io), 36 I/O26 1D10 (io), 37 I/O27 1D11 (io), 38 I/O28 1D12 (io), 39 I/O29 1D13 (io), 40 I/O30 1D14 (io), 41 I/O31 1D15 (io), 44 I/O32 1A15 (io), 45 I/O33 1A14 (io), 46 I/O34 1A13 (io), 47 I/O35 1A12 (io), 48 I/O36 1A11 (io), 49 I/O37 1A10 (io), 50 I/O38 1A9 (io), 51 I/O39 1A8 (io), 54 I/O40 1A7 (io), 55 I/O41 1A6 (io), 56 I/O42 1A5 (io), 57 I/O43 1A4 (io), 58 I/O44 1A3 (io), 59 I/O45 1A2 (io), 60 I/O46 1A1 (io), 61 I/O47 1A0 (io), 64 I/O48 1B0 (io), 65 I/O49 1B1 (io), 66 I/O50 1B2 (io), 67 I/O51 1B3 (io), 68 I/O52 1B4 (io), 69 I/O53 1B5 (io), 70 I/O54 1B6 (io), 71 I/O55 1B7 (io), 73 I/O56 1B8 (io), 74 I/O57 1B11 (io), 75 I/O58 1B12 (io), 76 I/O59 1B13 (io), 81 I/O60 2B13 (io), 82 I/O61 2B12 (io), 83 I/O62 2B11 (io), 84 I/O63 2B8 (io), 86 I/O64 2B7 (io), 87 I/O65 2B6 (io), 88 I/O66 2B5 (io), 89 I/O67 2B4 (io), 90 I/O68 2B3 (io), 91 I/O69 2B2 (io), 92 I/O70 2B1 (io), 93 I/O71 2B0 (io), 96 I/O72 2A0 (io), 97 I/O73 2A1 (io), 98 I/O74 2A2 (io), 99 I/O75 2A3 (io), 100 I/O76 2A4 (io), 101 I/O77 2A5 (io), 102 I/O78 2A6 (io), 103 I/O79 2A7 (io), 106 I/O80 2A8 (io), 107 I/O81 2A9 (io), 108 I/O82 2A10 (io), 109 I/O83 2A11 (io), 110 I/O84 2A12 (io), 111 I/O85 2A13 (io), 112 I/O86 2A14 (io), 113 I/O87 2A15 (io), 116 I/O88 2D15 (io), 117 I/O89 2D14 (io), 118 I/O90 2D13 (io), 119 I/O91 2D12 (io), 120 I/O92 2D11 (io), 121 I/O93 2D10 (io), 122 I/O94 2D9 (io), 123 I/O95 2D8 (io), 125 I/O96 2D7 (io), 126 I/O97 2D4 (io), 127 I/O98 2D3 (io), 128 I/O99 2D2 (io), 133 I/O100 3D2 (io), 134 I/O101 3D3 (io), 135 I/O102 3D4 (io), 136 I/O103 3D7 (io), 138 I/O104 3D8 (io), 139 I/O105 3D9 (io), 140 I/O106 3D10 (io), 141 I/O107 3D11 (io), 142 I/O108 3D12 (io), 143 I/O109 3D13 (io), 144 I/O110 3D14 (io), 145 I/O111 3D15 (io), 148 I/O112 3A13 (io), 149 I/O113 3A12 (io), 150 I/O114 3A11 (io), 151 I/O115 3A8 (io), 152 I/O116 3A7 (io), 153 I/O117 3A4 (io), 154 I/O118 3A3 (io), 155 I/O119 3A2 (io), 158 I/O120 3B2 (io), 159 I/O121 3B3 (io), 160 I/O122 3B4 (io), 161 I/O123 3B7 (io), 162 I/O124 3B8 (io), 163 I/O125 3B11 (io), 164 I/O126 3B12 (io), 165 I/O127 3B13 (io), 168 I/O128 4B15 (io), 169 I/O129 4B14 (io), 170 I/O130 4B13 (io), 171 I/O131 4B12 (io), 172 I/O132 4B11 (io), 173 I/O133 4B10 (io), 174 I/O134 4B9 (io), 175 I/O135 4B8 (io), 177 I/O136 4B7 (io), 178 I/O137 4B4 (io), 179 I/O138 4B3 (io), 180 I/O139 4B2 (io), 185 I/O140 4A2 (io), 186 I/O141 4A3 (io), 187 I/O142 4A4 (io), 188 I/O143 4A7 (io), 190 I/O144 4A8 (io), 191 I/O145 4A9 (io), 192 I/O146 4A10 (io), 193 I/O147 4A11 (io), 194 I/O148 4A12 (io), 195 I/O149 4A13 (io), 196 I/O150 4A14 (io), 197 I/O151 4A15 (io), 200 I/O152 0B13 (io), 201 I/O153 0B12 (io), 202 I/O154 0B11 (io), 203 I/O155 0B8 (io), 204 I/O156 0B7 (io), 205 I/O157 0B4 (io), 206 I/O158 0B3 (io), 207 I/O159 0B2 (io)
part B pins: 1 TDI (in), 10 VCC (power), 11 GND (power), 20 GND (power), 25 I0/CLK0 (in), 26 VCC (power), 27 GND (power), 28 I1/CLK1 (in), 33 GND (power), 42 GND (power), 43 VCC (power), 52 TCK (in), 53 GND (power), 62 GND (power), 63 VCC (power), 72 GND (power), 77 VCC (power), 78 GND (power), 79 GND (power), 80 VCC (power), 85 GND (power), 94 VCC (power), 95 GND (power), 104 GND (power), 105 TMS (in), 114 VCC (power), 115 GND (power), 124 GND (power), 129 I2/CLK2 (in), 130 VCC (power), 131 GND (power), 132 I3/CLK3 (in), 137 GND (power), 146 GND (power), 147 VCC (power), 156 TDO (out), 157 GND (power), 166 GND (power), 167 VCC (power), 176 GND (power), 181 VCC (power), 182 GND (power), 183 GND (power), 184 VCC (power), 189 GND (power), 198 VCC (power), 199 GND (power), 208 GND (power)

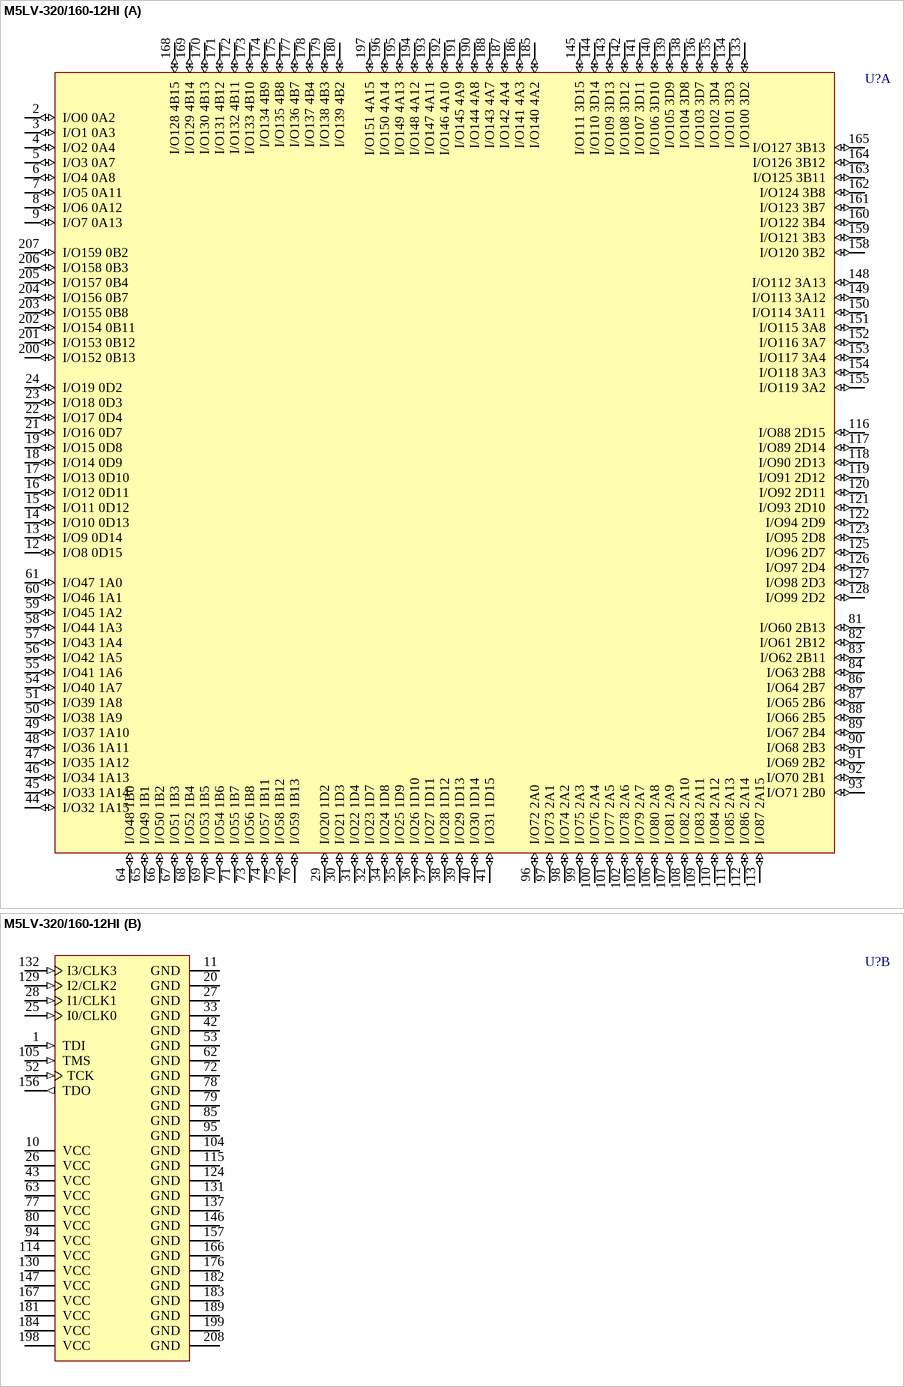
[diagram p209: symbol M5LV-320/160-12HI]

## M5LV-320/160-12HI
designator U?
High-Density and High-I/O Complex PLD
footprint MQFP208_N (Shrink QFP, 208-Leads, Body 27.7x27.7mm, Pitch 0.5mm, IPC Medium Density)
footprint MQFP208_L (Shrink QFP, 208-Leads, Body 27.7x27.7mm, Pitch 0.5mm, IPC High Density)
footprint MQFP208_M (Shrink QFP, 208-Leads, Body 27.7x27.7mm, Pitch 0.5mm, IPC Low Density)
3D model M5LV-MQFP208 (208-Pin Shrink Quad Flat Pack 0.5 mm Pitch)
part A pins: 2 I/O0 0A2 (io), 3 I/O1 0A3 (io), 4 I/O2 0A4 (io), 5 I/O3 0A7 (io), 6 I/O4 0A8 (io), 7 I/O5 0A11 (io), 8 I/O6 0A12 (io), 9 I/O7 0A13 (io), 12 I/O8 0D15 (io), 13 I/O9 0D14 (io), 14 I/O10 0D13 (io), 15 I/O11 0D12 (io), 16 I/O12 0D11 (io), 17 I/O13 0D10 (io), 18 I/O14 0D9 (io), 19 I/O15 0D8 (io), 21 I/O16 0D7 (io), 22 I/O17 0D4 (io), 23 I/O18 0D3 (io), 24 I/O19 0D2 (io), 29 I/O20 1D2 (io), 30 I/O21 1D3 (io), 31 I/O22 1D4 (io), 32 I/O23 1D7 (io), 34 I/O24 1D8 (io), 35 I/O25 1D9 (io), 36 I/O26 1D10 (io), 37 I/O27 1D11 (io), 38 I/O28 1D12 (io), 39 I/O29 1D13 (io), 40 I/O30 1D14 (io), 41 I/O31 1D15 (io), 44 I/O32 1A15 (io), 45 I/O33 1A14 (io), 46 I/O34 1A13 (io), 47 I/O35 1A12 (io), 48 I/O36 1A11 (io), 49 I/O37 1A10 (io), 50 I/O38 1A9 (io), 51 I/O39 1A8 (io), 54 I/O40 1A7 (io), 55 I/O41 1A6 (io), 56 I/O42 1A5 (io), 57 I/O43 1A4 (io), 58 I/O44 1A3 (io), 59 I/O45 1A2 (io), 60 I/O46 1A1 (io), 61 I/O47 1A0 (io), 64 I/O48 1B0 (io), 65 I/O49 1B1 (io), 66 I/O50 1B2 (io), 67 I/O51 1B3 (io), 68 I/O52 1B4 (io), 69 I/O53 1B5 (io), 70 I/O54 1B6 (io), 71 I/O55 1B7 (io), 73 I/O56 1B8 (io), 74 I/O57 1B11 (io), 75 I/O58 1B12 (io), 76 I/O59 1B13 (io), 81 I/O60 2B13 (io), 82 I/O61 2B12 (io), 83 I/O62 2B11 (io), 84 I/O63 2B8 (io), 86 I/O64 2B7 (io), 87 I/O65 2B6 (io), 88 I/O66 2B5 (io), 89 I/O67 2B4 (io), 90 I/O68 2B3 (io), 91 I/O69 2B2 (io), 92 I/O70 2B1 (io), 93 I/O71 2B0 (io), 96 I/O72 2A0 (io), 97 I/O73 2A1 (io), 98 I/O74 2A2 (io), 99 I/O75 2A3 (io), 100 I/O76 2A4 (io), 101 I/O77 2A5 (io), 102 I/O78 2A6 (io), 103 I/O79 2A7 (io), 106 I/O80 2A8 (io), 107 I/O81 2A9 (io), 108 I/O82 2A10 (io), 109 I/O83 2A11 (io), 110 I/O84 2A12 (io), 111 I/O85 2A13 (io), 112 I/O86 2A14 (io), 113 I/O87 2A15 (io), 116 I/O88 2D15 (io), 117 I/O89 2D14 (io), 118 I/O90 2D13 (io), 119 I/O91 2D12 (io), 120 I/O92 2D11 (io), 121 I/O93 2D10 (io), 122 I/O94 2D9 (io), 123 I/O95 2D8 (io), 125 I/O96 2D7 (io), 126 I/O97 2D4 (io), 127 I/O98 2D3 (io), 128 I/O99 2D2 (io), 133 I/O100 3D2 (io), 134 I/O101 3D3 (io), 135 I/O102 3D4 (io), 136 I/O103 3D7 (io), 138 I/O104 3D8 (io), 139 I/O105 3D9 (io), 140 I/O106 3D10 (io), 141 I/O107 3D11 (io), 142 I/O108 3D12 (io), 143 I/O109 3D13 (io), 144 I/O110 3D14 (io), 145 I/O111 3D15 (io), 148 I/O112 3A13 (io), 149 I/O113 3A12 (io), 150 I/O114 3A11 (io), 151 I/O115 3A8 (io), 152 I/O116 3A7 (io), 153 I/O117 3A4 (io), 154 I/O118 3A3 (io), 155 I/O119 3A2 (io), 158 I/O120 3B2 (io), 159 I/O121 3B3 (io), 160 I/O122 3B4 (io), 161 I/O123 3B7 (io), 162 I/O124 3B8 (io), 163 I/O125 3B11 (io), 164 I/O126 3B12 (io), 165 I/O127 3B13 (io), 168 I/O128 4B15 (io), 169 I/O129 4B14 (io), 170 I/O130 4B13 (io), 171 I/O131 4B12 (io), 172 I/O132 4B11 (io), 173 I/O133 4B10 (io), 174 I/O134 4B9 (io), 175 I/O135 4B8 (io), 177 I/O136 4B7 (io), 178 I/O137 4B4 (io), 179 I/O138 4B3 (io), 180 I/O139 4B2 (io), 185 I/O140 4A2 (io), 186 I/O141 4A3 (io), 187 I/O142 4A4 (io), 188 I/O143 4A7 (io), 190 I/O144 4A8 (io), 191 I/O145 4A9 (io), 192 I/O146 4A10 (io), 193 I/O147 4A11 (io), 194 I/O148 4A12 (io), 195 I/O149 4A13 (io), 196 I/O150 4A14 (io), 197 I/O151 4A15 (io), 200 I/O152 0B13 (io), 201 I/O153 0B12 (io), 202 I/O154 0B11 (io), 203 I/O155 0B8 (io), 204 I/O156 0B7 (io), 205 I/O157 0B4 (io), 206 I/O158 0B3 (io), 207 I/O159 0B2 (io)
part B pins: 1 TDI (in), 10 VCC (power), 11 GND (power), 20 GND (power), 25 I0/CLK0 (in), 26 VCC (power), 27 GND (power), 28 I1/CLK1 (in), 33 GND (power), 42 GND (power), 43 VCC (power), 52 TCK (in), 53 GND (power), 62 GND (power), 63 VCC (power), 72 GND (power), 77 VCC (power), 78 GND (power), 79 GND (power), 80 VCC (power), 85 GND (power), 94 VCC (power), 95 GND (power), 104 GND (power), 105 TMS (in), 114 VCC (power), 115 GND (power), 124 GND (power), 129 I2/CLK2 (in), 130 VCC (power), 131 GND (power), 132 I3/CLK3 (in), 137 GND (power), 146 GND (power), 147 VCC (power), 156 TDO (out), 157 GND (power), 166 GND (power), 167 VCC (power), 176 GND (power), 181 VCC (power), 182 GND (power), 183 GND (power), 184 VCC (power), 189 GND (power), 198 VCC (power), 199 GND (power), 208 GND (power)

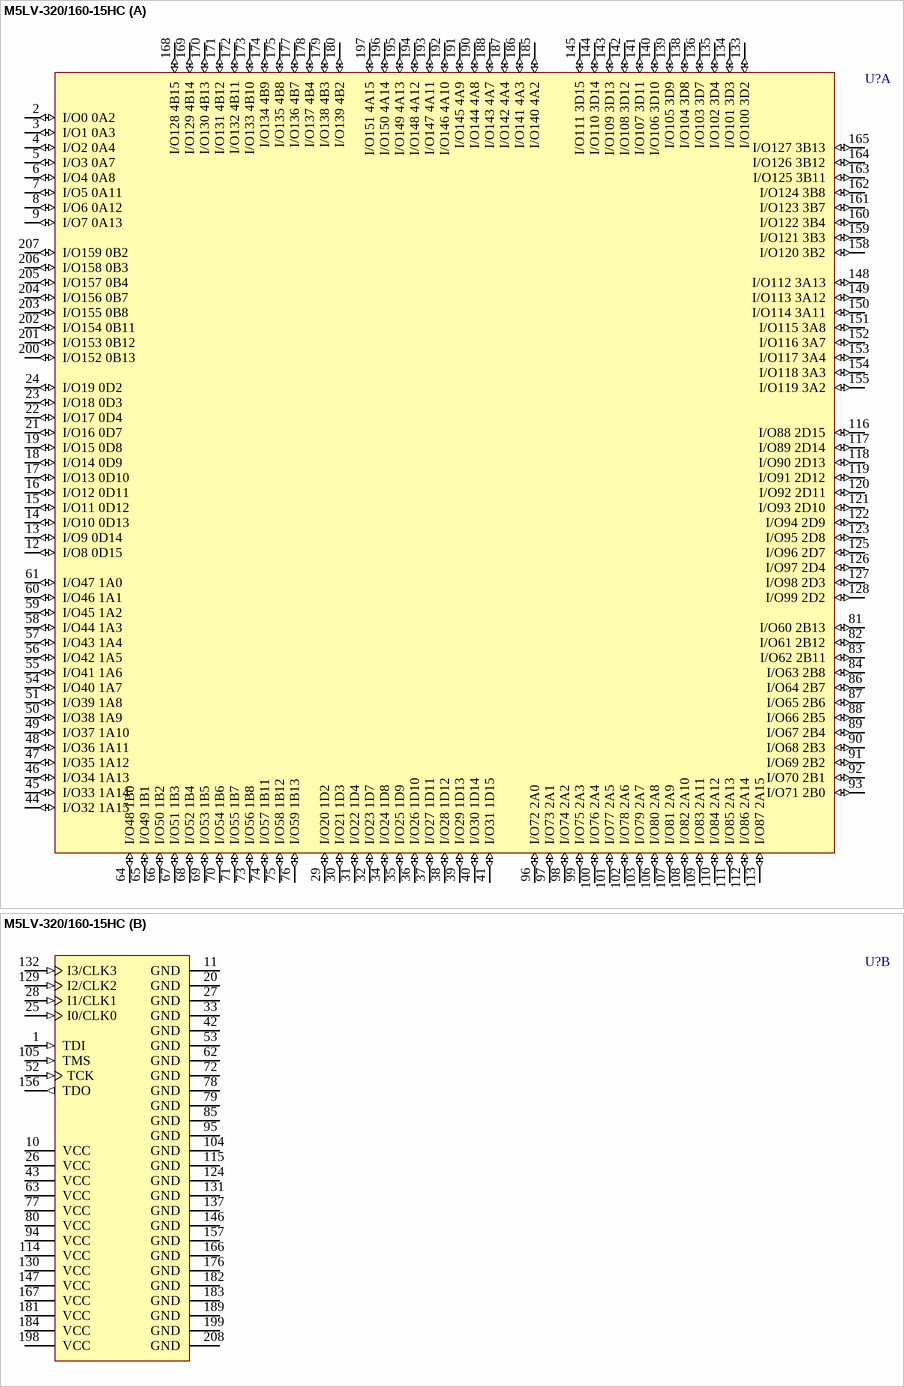
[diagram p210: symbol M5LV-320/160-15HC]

## M5LV-320/160-15HC
designator U?
High-Density and High-I/O Complex PLD
footprint MQFP208_N (Shrink QFP, 208-Leads, Body 27.7x27.7mm, Pitch 0.5mm, IPC Medium Density)
footprint MQFP208_L (Shrink QFP, 208-Leads, Body 27.7x27.7mm, Pitch 0.5mm, IPC High Density)
footprint MQFP208_M (Shrink QFP, 208-Leads, Body 27.7x27.7mm, Pitch 0.5mm, IPC Low Density)
3D model M5LV-MQFP208 (208-Pin Shrink Quad Flat Pack 0.5 mm Pitch)
part A pins: 2 I/O0 0A2 (io), 3 I/O1 0A3 (io), 4 I/O2 0A4 (io), 5 I/O3 0A7 (io), 6 I/O4 0A8 (io), 7 I/O5 0A11 (io), 8 I/O6 0A12 (io), 9 I/O7 0A13 (io), 12 I/O8 0D15 (io), 13 I/O9 0D14 (io), 14 I/O10 0D13 (io), 15 I/O11 0D12 (io), 16 I/O12 0D11 (io), 17 I/O13 0D10 (io), 18 I/O14 0D9 (io), 19 I/O15 0D8 (io), 21 I/O16 0D7 (io), 22 I/O17 0D4 (io), 23 I/O18 0D3 (io), 24 I/O19 0D2 (io), 29 I/O20 1D2 (io), 30 I/O21 1D3 (io), 31 I/O22 1D4 (io), 32 I/O23 1D7 (io), 34 I/O24 1D8 (io), 35 I/O25 1D9 (io), 36 I/O26 1D10 (io), 37 I/O27 1D11 (io), 38 I/O28 1D12 (io), 39 I/O29 1D13 (io), 40 I/O30 1D14 (io), 41 I/O31 1D15 (io), 44 I/O32 1A15 (io), 45 I/O33 1A14 (io), 46 I/O34 1A13 (io), 47 I/O35 1A12 (io), 48 I/O36 1A11 (io), 49 I/O37 1A10 (io), 50 I/O38 1A9 (io), 51 I/O39 1A8 (io), 54 I/O40 1A7 (io), 55 I/O41 1A6 (io), 56 I/O42 1A5 (io), 57 I/O43 1A4 (io), 58 I/O44 1A3 (io), 59 I/O45 1A2 (io), 60 I/O46 1A1 (io), 61 I/O47 1A0 (io), 64 I/O48 1B0 (io), 65 I/O49 1B1 (io), 66 I/O50 1B2 (io), 67 I/O51 1B3 (io), 68 I/O52 1B4 (io), 69 I/O53 1B5 (io), 70 I/O54 1B6 (io), 71 I/O55 1B7 (io), 73 I/O56 1B8 (io), 74 I/O57 1B11 (io), 75 I/O58 1B12 (io), 76 I/O59 1B13 (io), 81 I/O60 2B13 (io), 82 I/O61 2B12 (io), 83 I/O62 2B11 (io), 84 I/O63 2B8 (io), 86 I/O64 2B7 (io), 87 I/O65 2B6 (io), 88 I/O66 2B5 (io), 89 I/O67 2B4 (io), 90 I/O68 2B3 (io), 91 I/O69 2B2 (io), 92 I/O70 2B1 (io), 93 I/O71 2B0 (io), 96 I/O72 2A0 (io), 97 I/O73 2A1 (io), 98 I/O74 2A2 (io), 99 I/O75 2A3 (io), 100 I/O76 2A4 (io), 101 I/O77 2A5 (io), 102 I/O78 2A6 (io), 103 I/O79 2A7 (io), 106 I/O80 2A8 (io), 107 I/O81 2A9 (io), 108 I/O82 2A10 (io), 109 I/O83 2A11 (io), 110 I/O84 2A12 (io), 111 I/O85 2A13 (io), 112 I/O86 2A14 (io), 113 I/O87 2A15 (io), 116 I/O88 2D15 (io), 117 I/O89 2D14 (io), 118 I/O90 2D13 (io), 119 I/O91 2D12 (io), 120 I/O92 2D11 (io), 121 I/O93 2D10 (io), 122 I/O94 2D9 (io), 123 I/O95 2D8 (io), 125 I/O96 2D7 (io), 126 I/O97 2D4 (io), 127 I/O98 2D3 (io), 128 I/O99 2D2 (io), 133 I/O100 3D2 (io), 134 I/O101 3D3 (io), 135 I/O102 3D4 (io), 136 I/O103 3D7 (io), 138 I/O104 3D8 (io), 139 I/O105 3D9 (io), 140 I/O106 3D10 (io), 141 I/O107 3D11 (io), 142 I/O108 3D12 (io), 143 I/O109 3D13 (io), 144 I/O110 3D14 (io), 145 I/O111 3D15 (io), 148 I/O112 3A13 (io), 149 I/O113 3A12 (io), 150 I/O114 3A11 (io), 151 I/O115 3A8 (io), 152 I/O116 3A7 (io), 153 I/O117 3A4 (io), 154 I/O118 3A3 (io), 155 I/O119 3A2 (io), 158 I/O120 3B2 (io), 159 I/O121 3B3 (io), 160 I/O122 3B4 (io), 161 I/O123 3B7 (io), 162 I/O124 3B8 (io), 163 I/O125 3B11 (io), 164 I/O126 3B12 (io), 165 I/O127 3B13 (io), 168 I/O128 4B15 (io), 169 I/O129 4B14 (io), 170 I/O130 4B13 (io), 171 I/O131 4B12 (io), 172 I/O132 4B11 (io), 173 I/O133 4B10 (io), 174 I/O134 4B9 (io), 175 I/O135 4B8 (io), 177 I/O136 4B7 (io), 178 I/O137 4B4 (io), 179 I/O138 4B3 (io), 180 I/O139 4B2 (io), 185 I/O140 4A2 (io), 186 I/O141 4A3 (io), 187 I/O142 4A4 (io), 188 I/O143 4A7 (io), 190 I/O144 4A8 (io), 191 I/O145 4A9 (io), 192 I/O146 4A10 (io), 193 I/O147 4A11 (io), 194 I/O148 4A12 (io), 195 I/O149 4A13 (io), 196 I/O150 4A14 (io), 197 I/O151 4A15 (io), 200 I/O152 0B13 (io), 201 I/O153 0B12 (io), 202 I/O154 0B11 (io), 203 I/O155 0B8 (io), 204 I/O156 0B7 (io), 205 I/O157 0B4 (io), 206 I/O158 0B3 (io), 207 I/O159 0B2 (io)
part B pins: 1 TDI (in), 10 VCC (power), 11 GND (power), 20 GND (power), 25 I0/CLK0 (in), 26 VCC (power), 27 GND (power), 28 I1/CLK1 (in), 33 GND (power), 42 GND (power), 43 VCC (power), 52 TCK (in), 53 GND (power), 62 GND (power), 63 VCC (power), 72 GND (power), 77 VCC (power), 78 GND (power), 79 GND (power), 80 VCC (power), 85 GND (power), 94 VCC (power), 95 GND (power), 104 GND (power), 105 TMS (in), 114 VCC (power), 115 GND (power), 124 GND (power), 129 I2/CLK2 (in), 130 VCC (power), 131 GND (power), 132 I3/CLK3 (in), 137 GND (power), 146 GND (power), 147 VCC (power), 156 TDO (out), 157 GND (power), 166 GND (power), 167 VCC (power), 176 GND (power), 181 VCC (power), 182 GND (power), 183 GND (power), 184 VCC (power), 189 GND (power), 198 VCC (power), 199 GND (power), 208 GND (power)

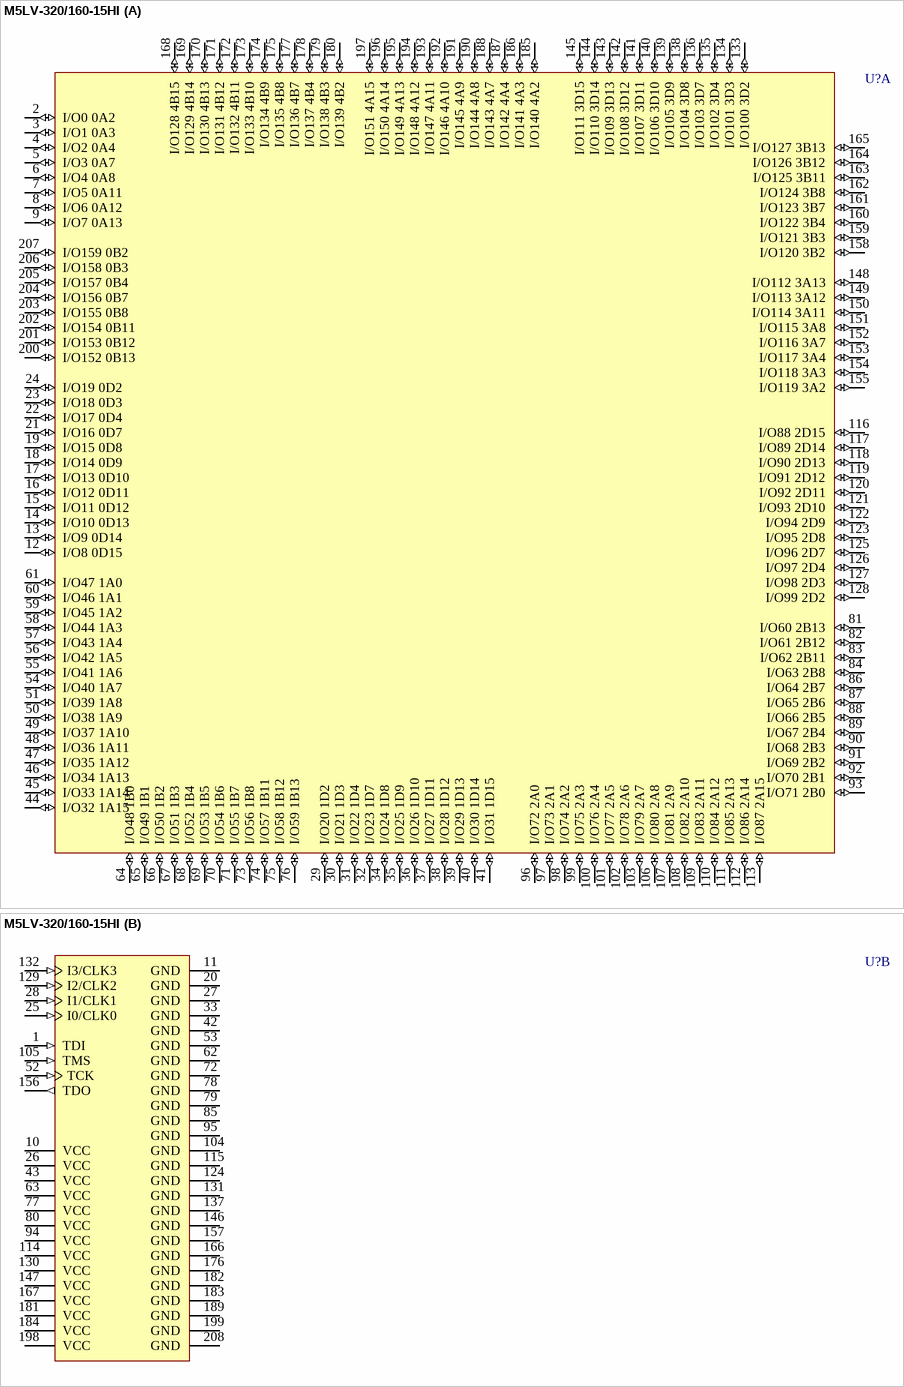
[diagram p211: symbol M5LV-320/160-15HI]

## M5LV-320/160-15HI
designator U?
High-Density and High-I/O Complex PLD
footprint MQFP208_N (Shrink QFP, 208-Leads, Body 27.7x27.7mm, Pitch 0.5mm, IPC Medium Density)
footprint MQFP208_L (Shrink QFP, 208-Leads, Body 27.7x27.7mm, Pitch 0.5mm, IPC High Density)
footprint MQFP208_M (Shrink QFP, 208-Leads, Body 27.7x27.7mm, Pitch 0.5mm, IPC Low Density)
3D model M5LV-MQFP208 (208-Pin Shrink Quad Flat Pack 0.5 mm Pitch)
part A pins: 2 I/O0 0A2 (io), 3 I/O1 0A3 (io), 4 I/O2 0A4 (io), 5 I/O3 0A7 (io), 6 I/O4 0A8 (io), 7 I/O5 0A11 (io), 8 I/O6 0A12 (io), 9 I/O7 0A13 (io), 12 I/O8 0D15 (io), 13 I/O9 0D14 (io), 14 I/O10 0D13 (io), 15 I/O11 0D12 (io), 16 I/O12 0D11 (io), 17 I/O13 0D10 (io), 18 I/O14 0D9 (io), 19 I/O15 0D8 (io), 21 I/O16 0D7 (io), 22 I/O17 0D4 (io), 23 I/O18 0D3 (io), 24 I/O19 0D2 (io), 29 I/O20 1D2 (io), 30 I/O21 1D3 (io), 31 I/O22 1D4 (io), 32 I/O23 1D7 (io), 34 I/O24 1D8 (io), 35 I/O25 1D9 (io), 36 I/O26 1D10 (io), 37 I/O27 1D11 (io), 38 I/O28 1D12 (io), 39 I/O29 1D13 (io), 40 I/O30 1D14 (io), 41 I/O31 1D15 (io), 44 I/O32 1A15 (io), 45 I/O33 1A14 (io), 46 I/O34 1A13 (io), 47 I/O35 1A12 (io), 48 I/O36 1A11 (io), 49 I/O37 1A10 (io), 50 I/O38 1A9 (io), 51 I/O39 1A8 (io), 54 I/O40 1A7 (io), 55 I/O41 1A6 (io), 56 I/O42 1A5 (io), 57 I/O43 1A4 (io), 58 I/O44 1A3 (io), 59 I/O45 1A2 (io), 60 I/O46 1A1 (io), 61 I/O47 1A0 (io), 64 I/O48 1B0 (io), 65 I/O49 1B1 (io), 66 I/O50 1B2 (io), 67 I/O51 1B3 (io), 68 I/O52 1B4 (io), 69 I/O53 1B5 (io), 70 I/O54 1B6 (io), 71 I/O55 1B7 (io), 73 I/O56 1B8 (io), 74 I/O57 1B11 (io), 75 I/O58 1B12 (io), 76 I/O59 1B13 (io), 81 I/O60 2B13 (io), 82 I/O61 2B12 (io), 83 I/O62 2B11 (io), 84 I/O63 2B8 (io), 86 I/O64 2B7 (io), 87 I/O65 2B6 (io), 88 I/O66 2B5 (io), 89 I/O67 2B4 (io), 90 I/O68 2B3 (io), 91 I/O69 2B2 (io), 92 I/O70 2B1 (io), 93 I/O71 2B0 (io), 96 I/O72 2A0 (io), 97 I/O73 2A1 (io), 98 I/O74 2A2 (io), 99 I/O75 2A3 (io), 100 I/O76 2A4 (io), 101 I/O77 2A5 (io), 102 I/O78 2A6 (io), 103 I/O79 2A7 (io), 106 I/O80 2A8 (io), 107 I/O81 2A9 (io), 108 I/O82 2A10 (io), 109 I/O83 2A11 (io), 110 I/O84 2A12 (io), 111 I/O85 2A13 (io), 112 I/O86 2A14 (io), 113 I/O87 2A15 (io), 116 I/O88 2D15 (io), 117 I/O89 2D14 (io), 118 I/O90 2D13 (io), 119 I/O91 2D12 (io), 120 I/O92 2D11 (io), 121 I/O93 2D10 (io), 122 I/O94 2D9 (io), 123 I/O95 2D8 (io), 125 I/O96 2D7 (io), 126 I/O97 2D4 (io), 127 I/O98 2D3 (io), 128 I/O99 2D2 (io), 133 I/O100 3D2 (io), 134 I/O101 3D3 (io), 135 I/O102 3D4 (io), 136 I/O103 3D7 (io), 138 I/O104 3D8 (io), 139 I/O105 3D9 (io), 140 I/O106 3D10 (io), 141 I/O107 3D11 (io), 142 I/O108 3D12 (io), 143 I/O109 3D13 (io), 144 I/O110 3D14 (io), 145 I/O111 3D15 (io), 148 I/O112 3A13 (io), 149 I/O113 3A12 (io), 150 I/O114 3A11 (io), 151 I/O115 3A8 (io), 152 I/O116 3A7 (io), 153 I/O117 3A4 (io), 154 I/O118 3A3 (io), 155 I/O119 3A2 (io), 158 I/O120 3B2 (io), 159 I/O121 3B3 (io), 160 I/O122 3B4 (io), 161 I/O123 3B7 (io), 162 I/O124 3B8 (io), 163 I/O125 3B11 (io), 164 I/O126 3B12 (io), 165 I/O127 3B13 (io), 168 I/O128 4B15 (io), 169 I/O129 4B14 (io), 170 I/O130 4B13 (io), 171 I/O131 4B12 (io), 172 I/O132 4B11 (io), 173 I/O133 4B10 (io), 174 I/O134 4B9 (io), 175 I/O135 4B8 (io), 177 I/O136 4B7 (io), 178 I/O137 4B4 (io), 179 I/O138 4B3 (io), 180 I/O139 4B2 (io), 185 I/O140 4A2 (io), 186 I/O141 4A3 (io), 187 I/O142 4A4 (io), 188 I/O143 4A7 (io), 190 I/O144 4A8 (io), 191 I/O145 4A9 (io), 192 I/O146 4A10 (io), 193 I/O147 4A11 (io), 194 I/O148 4A12 (io), 195 I/O149 4A13 (io), 196 I/O150 4A14 (io), 197 I/O151 4A15 (io), 200 I/O152 0B13 (io), 201 I/O153 0B12 (io), 202 I/O154 0B11 (io), 203 I/O155 0B8 (io), 204 I/O156 0B7 (io), 205 I/O157 0B4 (io), 206 I/O158 0B3 (io), 207 I/O159 0B2 (io)
part B pins: 1 TDI (in), 10 VCC (power), 11 GND (power), 20 GND (power), 25 I0/CLK0 (in), 26 VCC (power), 27 GND (power), 28 I1/CLK1 (in), 33 GND (power), 42 GND (power), 43 VCC (power), 52 TCK (in), 53 GND (power), 62 GND (power), 63 VCC (power), 72 GND (power), 77 VCC (power), 78 GND (power), 79 GND (power), 80 VCC (power), 85 GND (power), 94 VCC (power), 95 GND (power), 104 GND (power), 105 TMS (in), 114 VCC (power), 115 GND (power), 124 GND (power), 129 I2/CLK2 (in), 130 VCC (power), 131 GND (power), 132 I3/CLK3 (in), 137 GND (power), 146 GND (power), 147 VCC (power), 156 TDO (out), 157 GND (power), 166 GND (power), 167 VCC (power), 176 GND (power), 181 VCC (power), 182 GND (power), 183 GND (power), 184 VCC (power), 189 GND (power), 198 VCC (power), 199 GND (power), 208 GND (power)

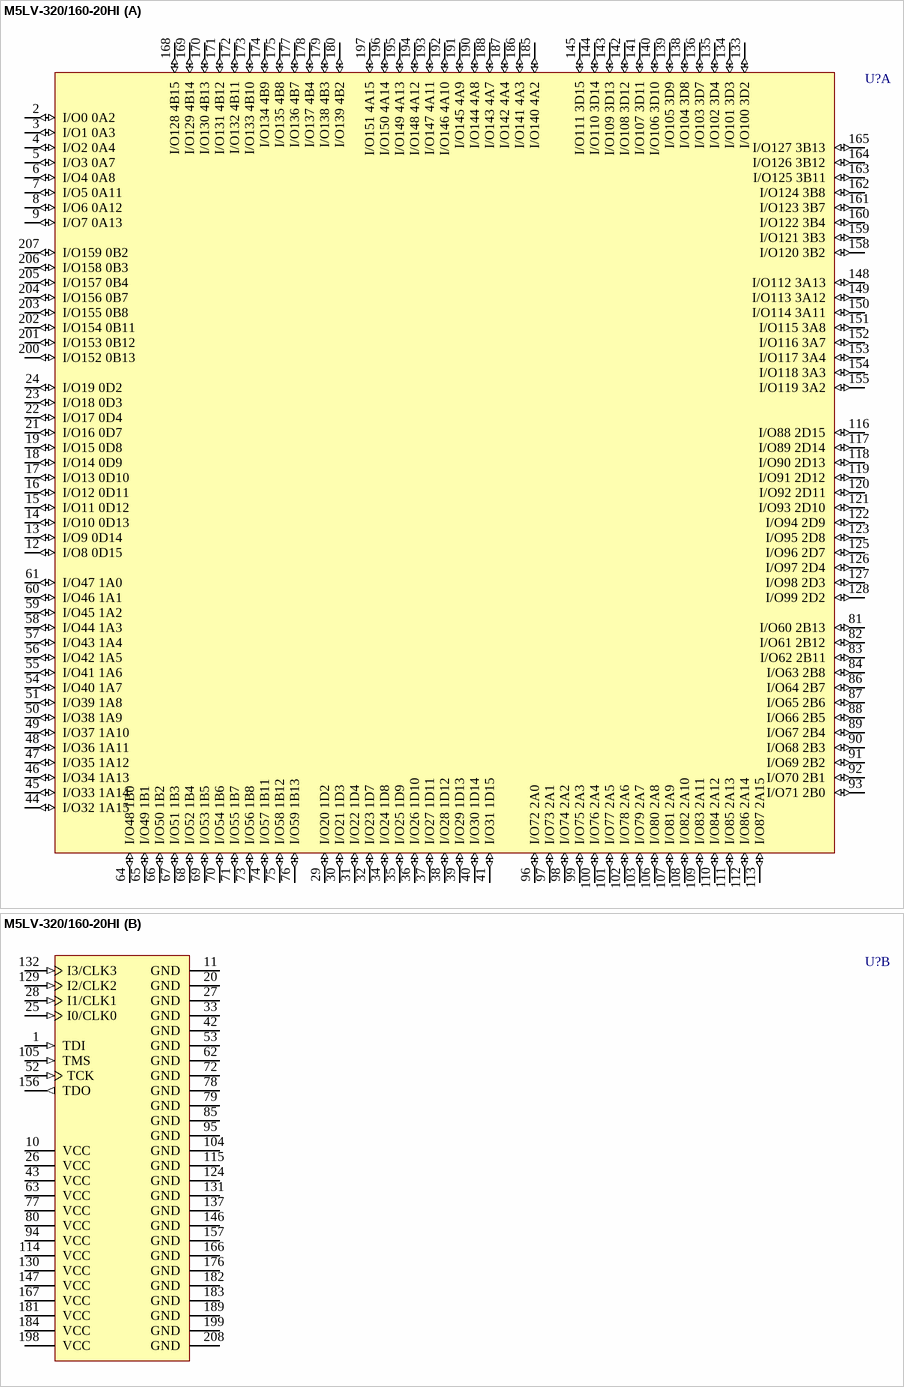
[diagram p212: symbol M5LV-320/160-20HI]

## M5LV-320/160-20HI
designator U?
High-Density and High-I/O Complex PLD
footprint MQFP208_N (Shrink QFP, 208-Leads, Body 27.7x27.7mm, Pitch 0.5mm, IPC Medium Density)
footprint MQFP208_L (Shrink QFP, 208-Leads, Body 27.7x27.7mm, Pitch 0.5mm, IPC High Density)
footprint MQFP208_M (Shrink QFP, 208-Leads, Body 27.7x27.7mm, Pitch 0.5mm, IPC Low Density)
3D model M5LV-MQFP208 (208-Pin Shrink Quad Flat Pack 0.5 mm Pitch)
part A pins: 2 I/O0 0A2 (io), 3 I/O1 0A3 (io), 4 I/O2 0A4 (io), 5 I/O3 0A7 (io), 6 I/O4 0A8 (io), 7 I/O5 0A11 (io), 8 I/O6 0A12 (io), 9 I/O7 0A13 (io), 12 I/O8 0D15 (io), 13 I/O9 0D14 (io), 14 I/O10 0D13 (io), 15 I/O11 0D12 (io), 16 I/O12 0D11 (io), 17 I/O13 0D10 (io), 18 I/O14 0D9 (io), 19 I/O15 0D8 (io), 21 I/O16 0D7 (io), 22 I/O17 0D4 (io), 23 I/O18 0D3 (io), 24 I/O19 0D2 (io), 29 I/O20 1D2 (io), 30 I/O21 1D3 (io), 31 I/O22 1D4 (io), 32 I/O23 1D7 (io), 34 I/O24 1D8 (io), 35 I/O25 1D9 (io), 36 I/O26 1D10 (io), 37 I/O27 1D11 (io), 38 I/O28 1D12 (io), 39 I/O29 1D13 (io), 40 I/O30 1D14 (io), 41 I/O31 1D15 (io), 44 I/O32 1A15 (io), 45 I/O33 1A14 (io), 46 I/O34 1A13 (io), 47 I/O35 1A12 (io), 48 I/O36 1A11 (io), 49 I/O37 1A10 (io), 50 I/O38 1A9 (io), 51 I/O39 1A8 (io), 54 I/O40 1A7 (io), 55 I/O41 1A6 (io), 56 I/O42 1A5 (io), 57 I/O43 1A4 (io), 58 I/O44 1A3 (io), 59 I/O45 1A2 (io), 60 I/O46 1A1 (io), 61 I/O47 1A0 (io), 64 I/O48 1B0 (io), 65 I/O49 1B1 (io), 66 I/O50 1B2 (io), 67 I/O51 1B3 (io), 68 I/O52 1B4 (io), 69 I/O53 1B5 (io), 70 I/O54 1B6 (io), 71 I/O55 1B7 (io), 73 I/O56 1B8 (io), 74 I/O57 1B11 (io), 75 I/O58 1B12 (io), 76 I/O59 1B13 (io), 81 I/O60 2B13 (io), 82 I/O61 2B12 (io), 83 I/O62 2B11 (io), 84 I/O63 2B8 (io), 86 I/O64 2B7 (io), 87 I/O65 2B6 (io), 88 I/O66 2B5 (io), 89 I/O67 2B4 (io), 90 I/O68 2B3 (io), 91 I/O69 2B2 (io), 92 I/O70 2B1 (io), 93 I/O71 2B0 (io), 96 I/O72 2A0 (io), 97 I/O73 2A1 (io), 98 I/O74 2A2 (io), 99 I/O75 2A3 (io), 100 I/O76 2A4 (io), 101 I/O77 2A5 (io), 102 I/O78 2A6 (io), 103 I/O79 2A7 (io), 106 I/O80 2A8 (io), 107 I/O81 2A9 (io), 108 I/O82 2A10 (io), 109 I/O83 2A11 (io), 110 I/O84 2A12 (io), 111 I/O85 2A13 (io), 112 I/O86 2A14 (io), 113 I/O87 2A15 (io), 116 I/O88 2D15 (io), 117 I/O89 2D14 (io), 118 I/O90 2D13 (io), 119 I/O91 2D12 (io), 120 I/O92 2D11 (io), 121 I/O93 2D10 (io), 122 I/O94 2D9 (io), 123 I/O95 2D8 (io), 125 I/O96 2D7 (io), 126 I/O97 2D4 (io), 127 I/O98 2D3 (io), 128 I/O99 2D2 (io), 133 I/O100 3D2 (io), 134 I/O101 3D3 (io), 135 I/O102 3D4 (io), 136 I/O103 3D7 (io), 138 I/O104 3D8 (io), 139 I/O105 3D9 (io), 140 I/O106 3D10 (io), 141 I/O107 3D11 (io), 142 I/O108 3D12 (io), 143 I/O109 3D13 (io), 144 I/O110 3D14 (io), 145 I/O111 3D15 (io), 148 I/O112 3A13 (io), 149 I/O113 3A12 (io), 150 I/O114 3A11 (io), 151 I/O115 3A8 (io), 152 I/O116 3A7 (io), 153 I/O117 3A4 (io), 154 I/O118 3A3 (io), 155 I/O119 3A2 (io), 158 I/O120 3B2 (io), 159 I/O121 3B3 (io), 160 I/O122 3B4 (io), 161 I/O123 3B7 (io), 162 I/O124 3B8 (io), 163 I/O125 3B11 (io), 164 I/O126 3B12 (io), 165 I/O127 3B13 (io), 168 I/O128 4B15 (io), 169 I/O129 4B14 (io), 170 I/O130 4B13 (io), 171 I/O131 4B12 (io), 172 I/O132 4B11 (io), 173 I/O133 4B10 (io), 174 I/O134 4B9 (io), 175 I/O135 4B8 (io), 177 I/O136 4B7 (io), 178 I/O137 4B4 (io), 179 I/O138 4B3 (io), 180 I/O139 4B2 (io), 185 I/O140 4A2 (io), 186 I/O141 4A3 (io), 187 I/O142 4A4 (io), 188 I/O143 4A7 (io), 190 I/O144 4A8 (io), 191 I/O145 4A9 (io), 192 I/O146 4A10 (io), 193 I/O147 4A11 (io), 194 I/O148 4A12 (io), 195 I/O149 4A13 (io), 196 I/O150 4A14 (io), 197 I/O151 4A15 (io), 200 I/O152 0B13 (io), 201 I/O153 0B12 (io), 202 I/O154 0B11 (io), 203 I/O155 0B8 (io), 204 I/O156 0B7 (io), 205 I/O157 0B4 (io), 206 I/O158 0B3 (io), 207 I/O159 0B2 (io)
part B pins: 1 TDI (in), 10 VCC (power), 11 GND (power), 20 GND (power), 25 I0/CLK0 (in), 26 VCC (power), 27 GND (power), 28 I1/CLK1 (in), 33 GND (power), 42 GND (power), 43 VCC (power), 52 TCK (in), 53 GND (power), 62 GND (power), 63 VCC (power), 72 GND (power), 77 VCC (power), 78 GND (power), 79 GND (power), 80 VCC (power), 85 GND (power), 94 VCC (power), 95 GND (power), 104 GND (power), 105 TMS (in), 114 VCC (power), 115 GND (power), 124 GND (power), 129 I2/CLK2 (in), 130 VCC (power), 131 GND (power), 132 I3/CLK3 (in), 137 GND (power), 146 GND (power), 147 VCC (power), 156 TDO (out), 157 GND (power), 166 GND (power), 167 VCC (power), 176 GND (power), 181 VCC (power), 182 GND (power), 183 GND (power), 184 VCC (power), 189 GND (power), 198 VCC (power), 199 GND (power), 208 GND (power)

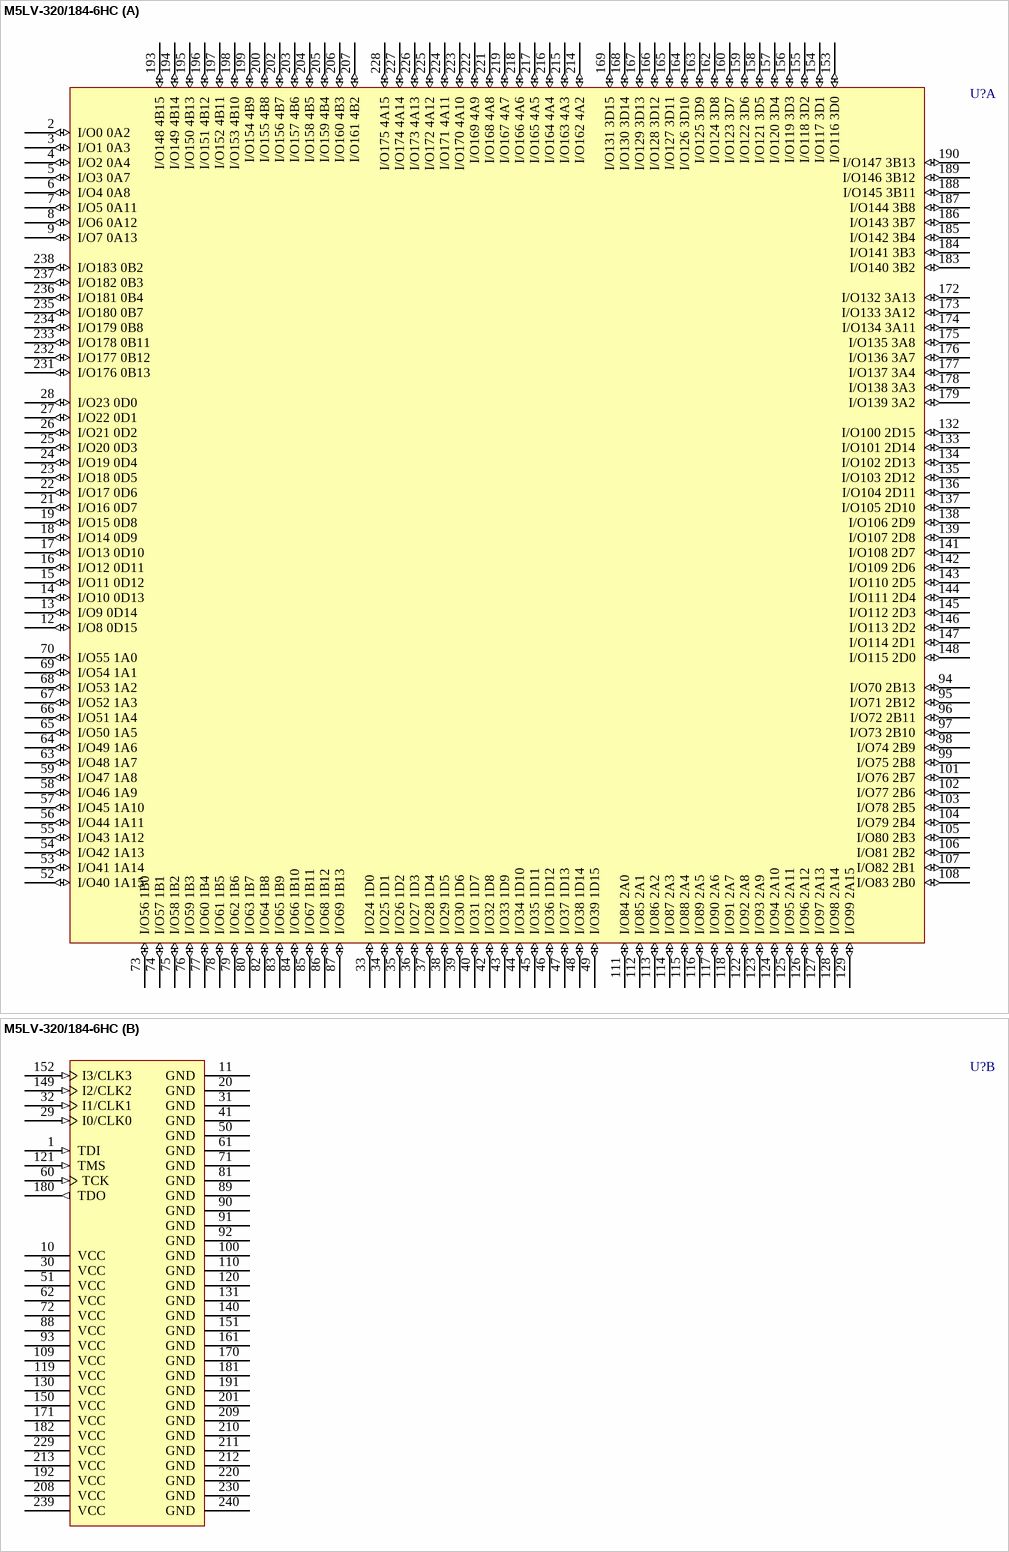
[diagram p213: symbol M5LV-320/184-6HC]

## M5LV-320/184-6HC
designator U?
High-Density and High-I/O Complex PLD
footprint PQFP240_N (Shrink QFP, 240-Leads, Body 32x32mm, Pitch 0.5mm, IPC Medium Density)
footprint PQFP240_L (Shrink QFP, 240-Leads, Body 32x32mm, Pitch 0.5mm, IPC High Density)
footprint PQFP240_M (Shrink QFP, 240-Leads, Body 32x32mm, Pitch 0.5mm, IPC Low Density)
3D model M5LV-PQFP240 (240-Pin Shrink Quad Flat Pack 0.5 mm Pitch)
part A pins: 2 I/O0 0A2 (io), 3 I/O1 0A3 (io), 4 I/O2 0A4 (io), 5 I/O3 0A7 (io), 6 I/O4 0A8 (io), 7 I/O5 0A11 (io), 8 I/O6 0A12 (io), 9 I/O7 0A13 (io), 12 I/O8 0D15 (io), 13 I/O9 0D14 (io), 14 I/O10 0D13 (io), 15 I/O11 0D12 (io), 16 I/O12 0D11 (io), 17 I/O13 0D10 (io), 18 I/O14 0D9 (io), 19 I/O15 0D8 (io), 21 I/O16 0D7 (io), 22 I/O17 0D6 (io), 23 I/O18 0D5 (io), 24 I/O19 0D4 (io), 25 I/O20 0D3 (io), 26 I/O21 0D2 (io), 27 I/O22 0D1 (io), 28 I/O23 0D0 (io), 33 I/O24 1D0 (io), 34 I/O25 1D1 (io), 35 I/O26 1D2 (io), 36 I/O27 1D3 (io), 37 I/O28 1D4 (io), 38 I/O29 1D5 (io), 39 I/O30 1D6 (io), 40 I/O31 1D7 (io), 42 I/O32 1D8 (io), 43 I/O33 1D9 (io), 44 I/O34 1D10 (io), 45 I/O35 1D11 (io), 46 I/O36 1D12 (io), 47 I/O37 1D13 (io), 48 I/O38 1D14 (io), 49 I/O39 1D15 (io), 52 I/O40 1A15 (io), 53 I/O41 1A14 (io), 54 I/O42 1A13 (io), 55 I/O43 1A12 (io), 56 I/O44 1A11 (io), 57 I/O45 1A10 (io), 58 I/O46 1A9 (io), 59 I/O47 1A8 (io), 63 I/O48 1A7 (io), 64 I/O49 1A6 (io), 65 I/O50 1A5 (io), 66 I/O51 1A4 (io), 67 I/O52 1A3 (io), 68 I/O53 1A2 (io), 69 I/O54 1A1 (io), 70 I/O55 1A0 (io), 73 I/O56 1B0 (io), 74 I/O57 1B1 (io), 75 I/O58 1B2 (io), 76 I/O59 1B3 (io), 77 I/O60 1B4 (io), 78 I/O61 1B5 (io), 79 I/O62 1B6 (io), 80 I/O63 1B7 (io), 82 I/O64 1B8 (io), 83 I/O65 1B9 (io), 84 I/O66 1B10 (io), 85 I/O67 1B11 (io), 86 I/O68 1B12 (io), 87 I/O69 1B13 (io), 94 I/O70 2B13 (io), 95 I/O71 2B12 (io), 96 I/O72 2B11 (io), 97 I/O73 2B10 (io), 98 I/O74 2B9 (io), 99 I/O75 2B8 (io), 101 I/O76 2B7 (io), 102 I/O77 2B6 (io), 103 I/O78 2B5 (io), 104 I/O79 2B4 (io), 105 I/O80 2B3 (io), 106 I/O81 2B2 (io), 107 I/O82 2B1 (io), 108 I/O83 2B0 (io), 111 I/O84 2A0 (io), 112 I/O85 2A1 (io), 113 I/O86 2A2 (io), 114 I/O87 2A3 (io), 115 I/O88 2A4 (io), 116 I/O89 2A5 (io), 117 I/O90 2A6 (io), 118 I/O91 2A7 (io), 122 I/O92 2A8 (io), 123 I/O93 2A9 (io), 124 I/O94 2A10 (io), 125 I/O95 2A11 (io), 126 I/O96 2A12 (io), 127 I/O97 2A13 (io), 128 I/O98 2A14 (io), 129 I/O99 2A15 (io), 132 I/O100 2D15 (io), 133 I/O101 2D14 (io), 134 I/O102 2D13 (io), 135 I/O103 2D12 (io), 136 I/O104 2D11 (io), 137 I/O105 2D10 (io), 138 I/O106 2D9 (io), 139 I/O107 2D8 (io), 141 I/O108 2D7 (io), 142 I/O109 2D6 (io), 143 I/O110 2D5 (io), 144 I/O111 2D4 (io), 145 I/O112 2D3 (io), 146 I/O113 2D2 (io), 147 I/O114 2D1 (io), 148 I/O115 2D0 (io), 153 I/O116 3D0 (io), 154 I/O117 3D1 (io), 155 I/O118 3D2 (io), 156 I/O119 3D3 (io), 157 I/O120 3D4 (io), 158 I/O121 3D5 (io), 159 I/O122 3D6 (io), 160 I/O123 3D7 (io), 162 I/O124 3D8 (io), 163 I/O125 3D9 (io), 164 I/O126 3D10 (io), 165 I/O127 3D11 (io), 166 I/O128 3D12 (io), 167 I/O129 3D13 (io), 168 I/O130 3D14 (io), 169 I/O131 3D15 (io), 172 I/O132 3A13 (io), 173 I/O133 3A12 (io), 174 I/O134 3A11 (io), 175 I/O135 3A8 (io), 176 I/O136 3A7 (io), 177 I/O137 3A4 (io), 178 I/O138 3A3 (io), 179 I/O139 3A2 (io), 183 I/O140 3B2 (io), 184 I/O141 3B3 (io), 185 I/O142 3B4 (io), 186 I/O143 3B7 (io), 187 I/O144 3B8 (io), 188 I/O145 3B11 (io), 189 I/O146 3B12 (io), 190 I/O147 3B13 (io), 193 I/O148 4B15 (io), 194 I/O149 4B14 (io), 195 I/O150 4B13 (io), 196 I/O151 4B12 (io), 197 I/O152 4B11 (io), 198 I/O153 4B10 (io), 199 I/O154 4B9 (io), 200 I/O155 4B8 (io), 202 I/O156 4B7 (io), 203 I/O157 4B6 (io), 204 I/O158 4B5 (io), 205 I/O159 4B4 (io), 206 I/O160 4B3 (io), 207 I/O161 4B2 (io), 214 I/O162 4A2 (io), 215 I/O163 4A3 (io), 216 I/O164 4A4 (io), 217 I/O165 4A5 (io), 218 I/O166 4A6 (io), 219 I/O167 4A7 (io), 221 I/O168 4A8 (io), 222 I/O169 4A9 (io), 223 I/O170 4A10 (io), 224 I/O171 4A11 (io), 225 I/O172 4A12 (io), 226 I/O173 4A13 (io), 227 I/O174 4A14 (io), 228 I/O175 4A15 (io), 231 I/O176 0B13 (io), 232 I/O177 0B12 (io), 233 I/O178 0B11 (io), 234 I/O179 0B8 (io), 235 I/O180 0B7 (io), 236 I/O181 0B4 (io), 237 I/O182 0B3 (io), 238 I/O183 0B2 (io)
part B pins: 1 TDI (in), 10 VCC (power), 11 GND (power), 20 GND (power), 29 I0/CLK0 (in), 30 VCC (power), 31 GND (power), 32 I1/CLK1 (in), 41 GND (power), 50 GND (power), 51 VCC (power), 60 TCK (in), 61 GND (power), 62 VCC (power), 71 GND (power), 72 VCC (power), 81 GND (power), 88 VCC (power), 89 GND (power), 90 GND (power), 91 GND (power), 92 GND (power), 93 VCC (power), 100 GND (power), 109 VCC (power), 110 GND (power), 119 VCC (power), 120 GND (power), 121 TMS (in), 130 VCC (power), 131 GND (power), 140 GND (power), 149 I2/CLK2 (in), 150 VCC (power), 151 GND (power), 152 I3/CLK3 (in), 161 GND (power), 170 GND (power), 171 VCC (power), 180 TDO (out), 181 GND (power), 182 VCC (power), 191 GND (power), 192 VCC (power), 201 GND (power), 208 VCC (power), 209 GND (power), 210 GND (power), 211 GND (power), 212 GND (power), 213 VCC (power), 220 GND (power), 229 VCC (power), 230 GND (power), 239 VCC (power), 240 GND (power)

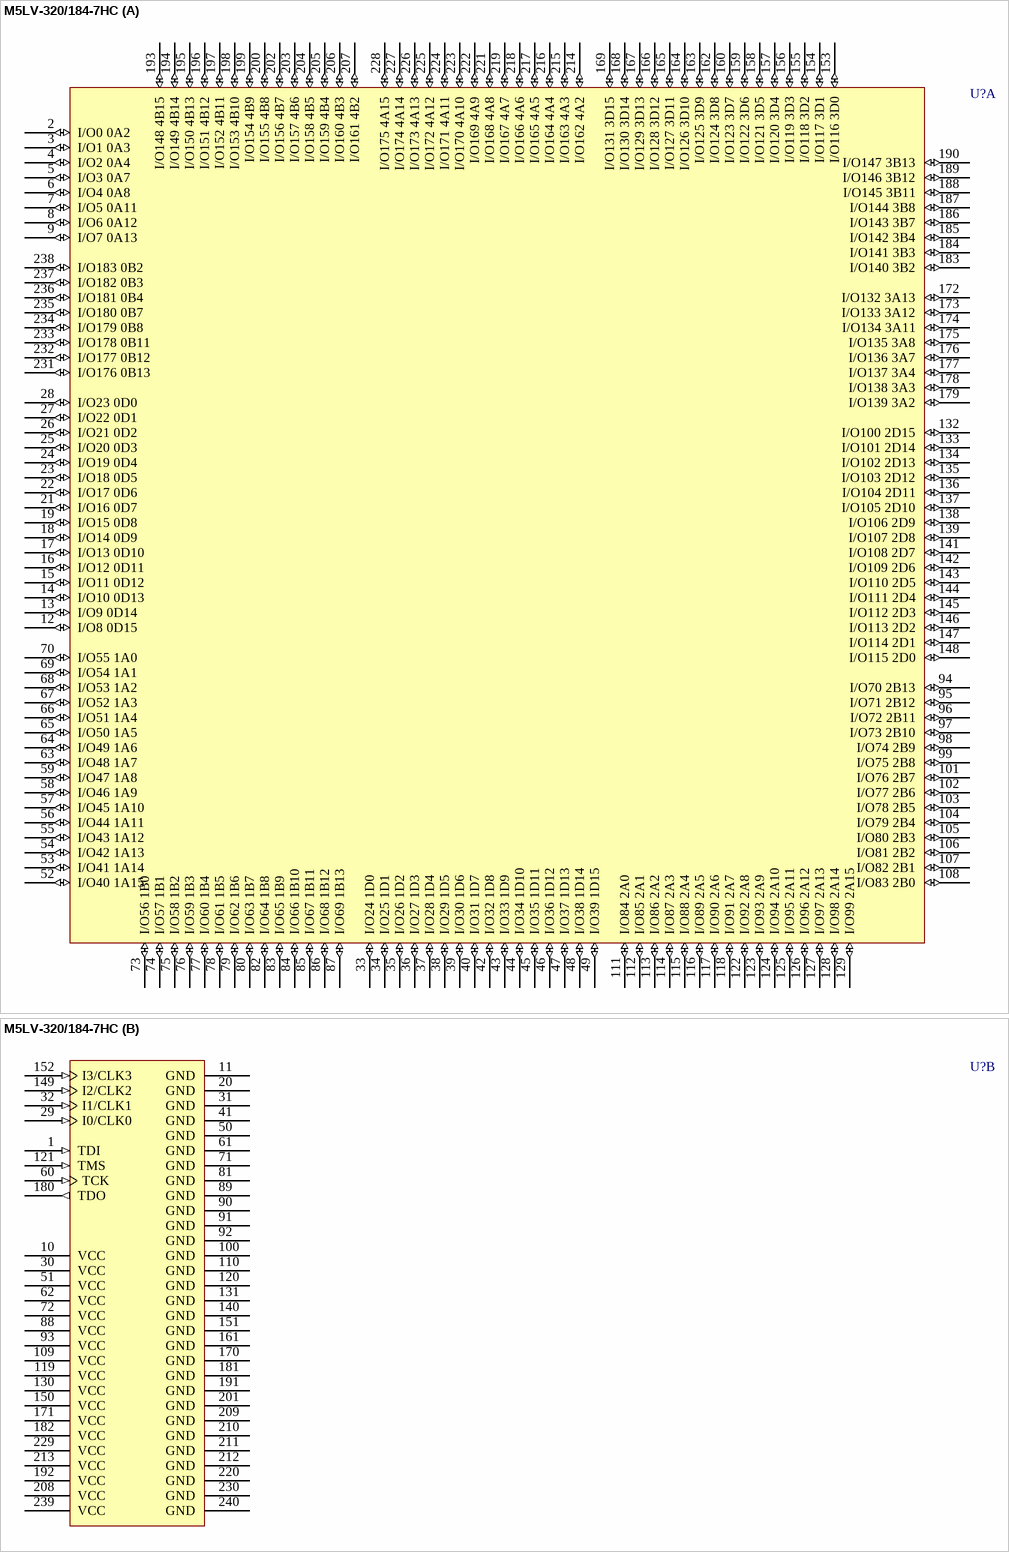
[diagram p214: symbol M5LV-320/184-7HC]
